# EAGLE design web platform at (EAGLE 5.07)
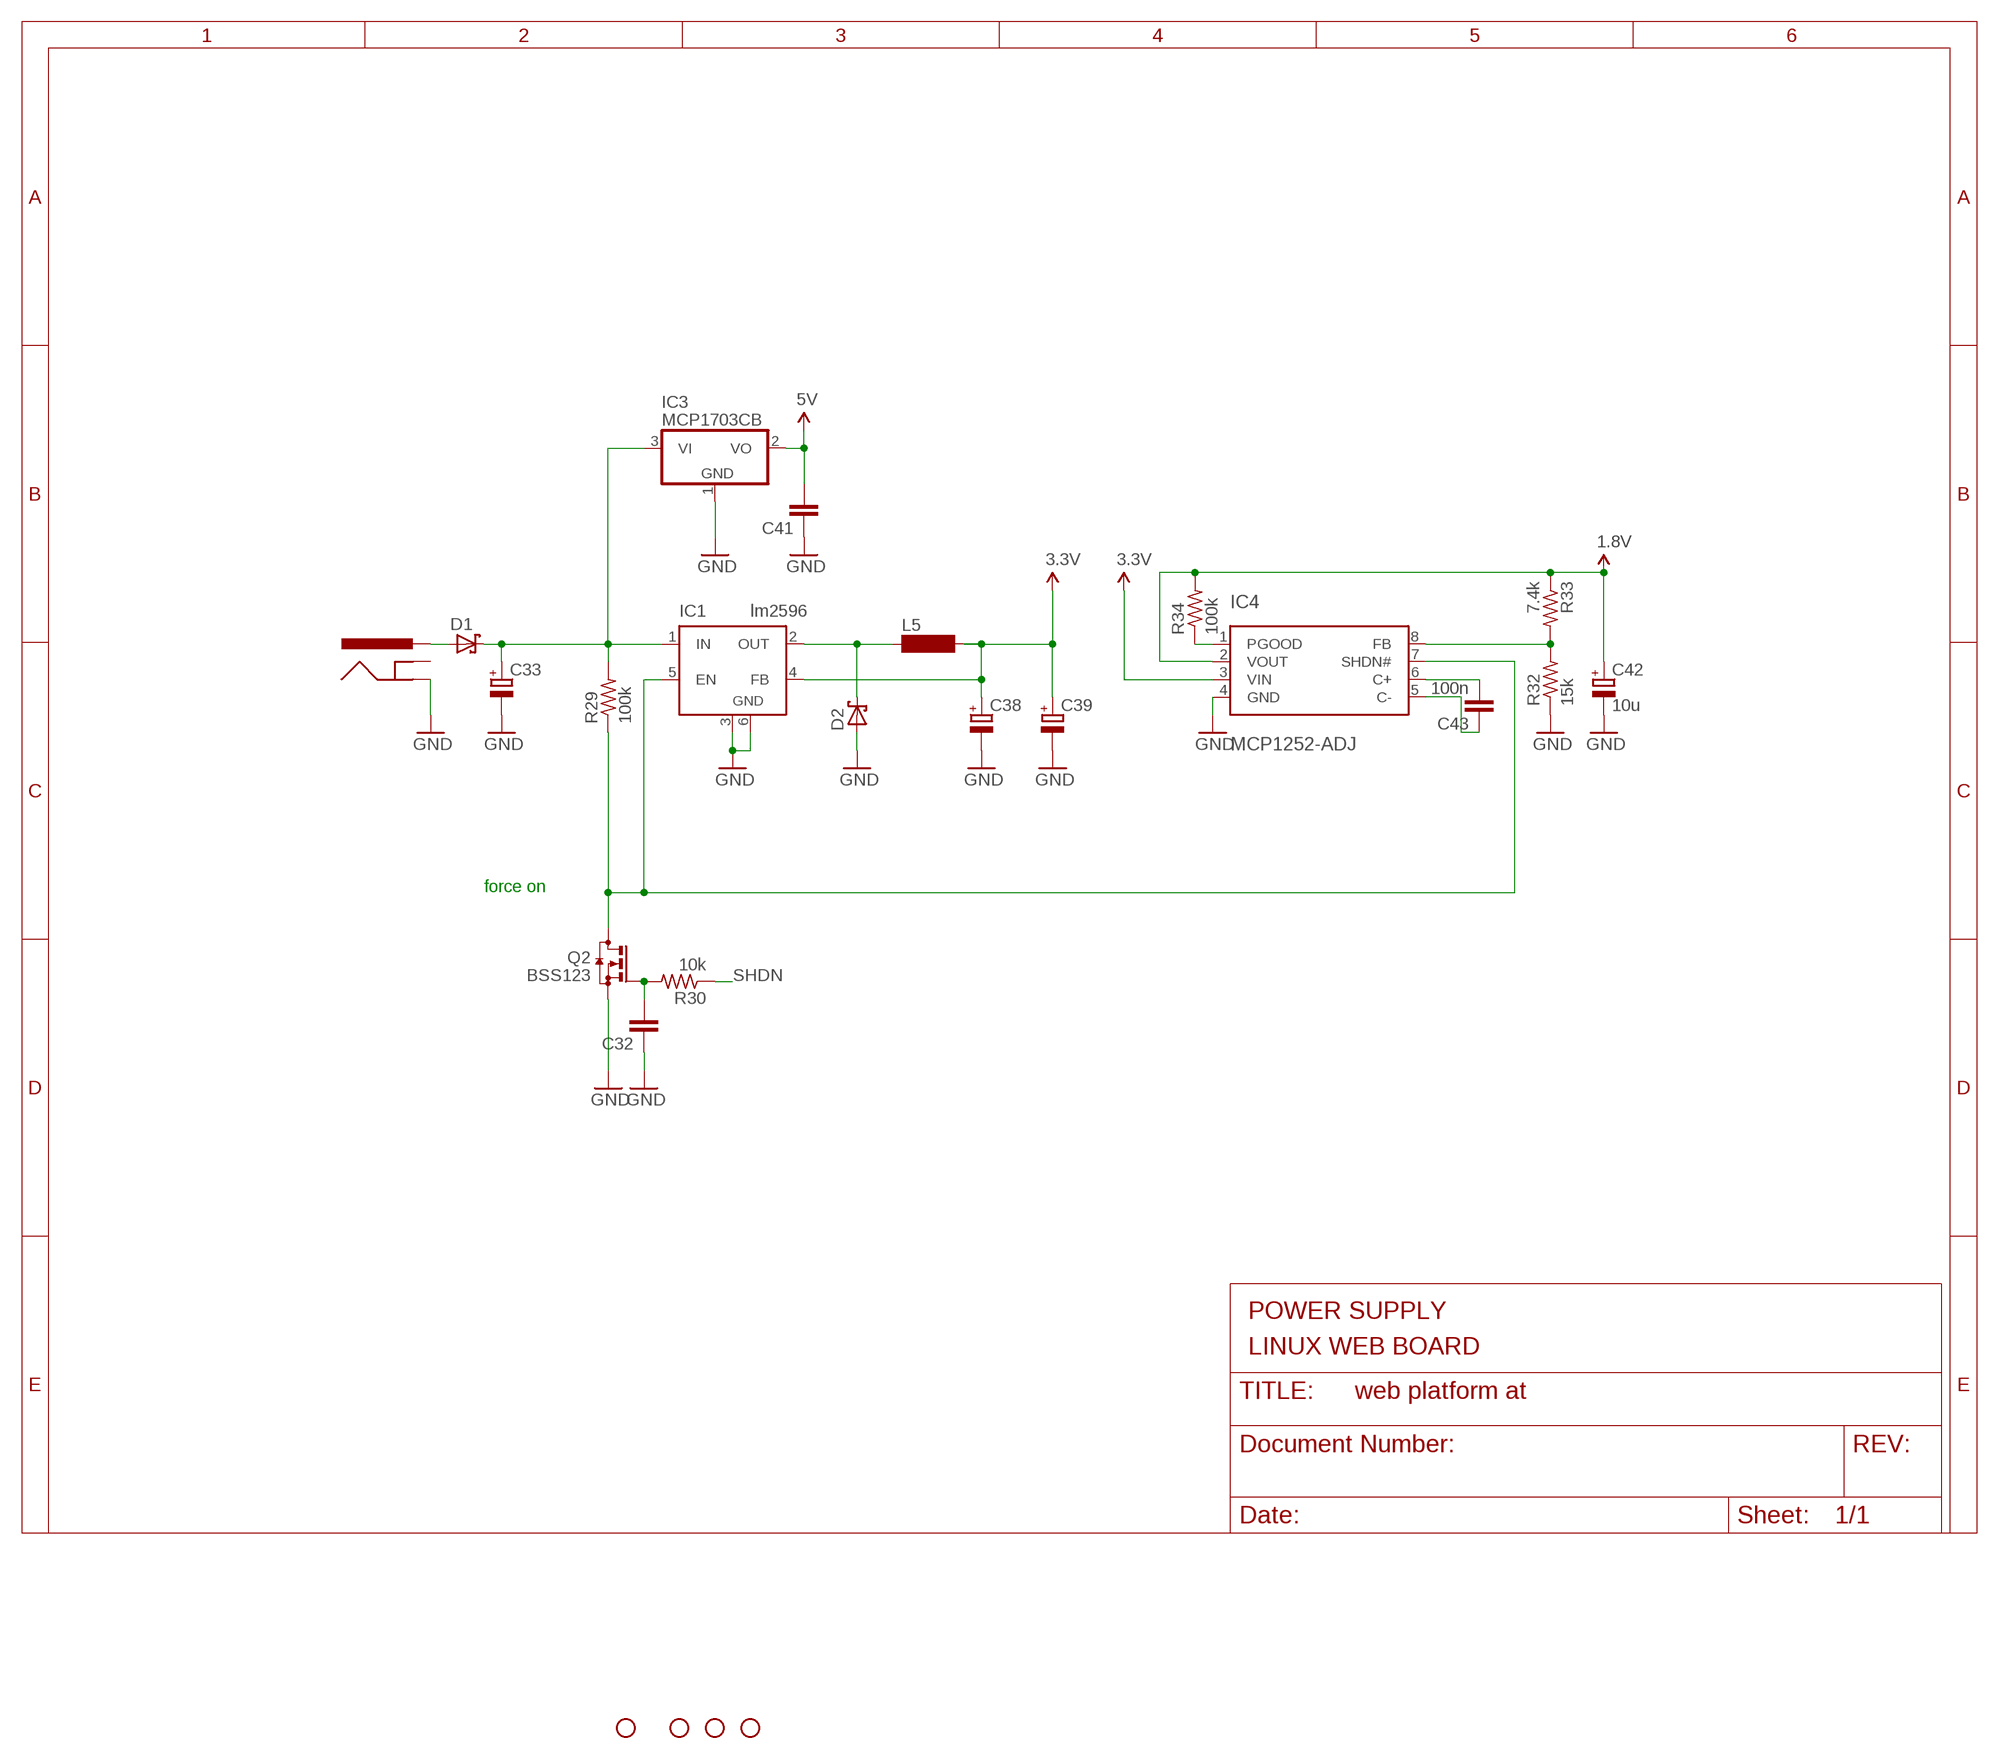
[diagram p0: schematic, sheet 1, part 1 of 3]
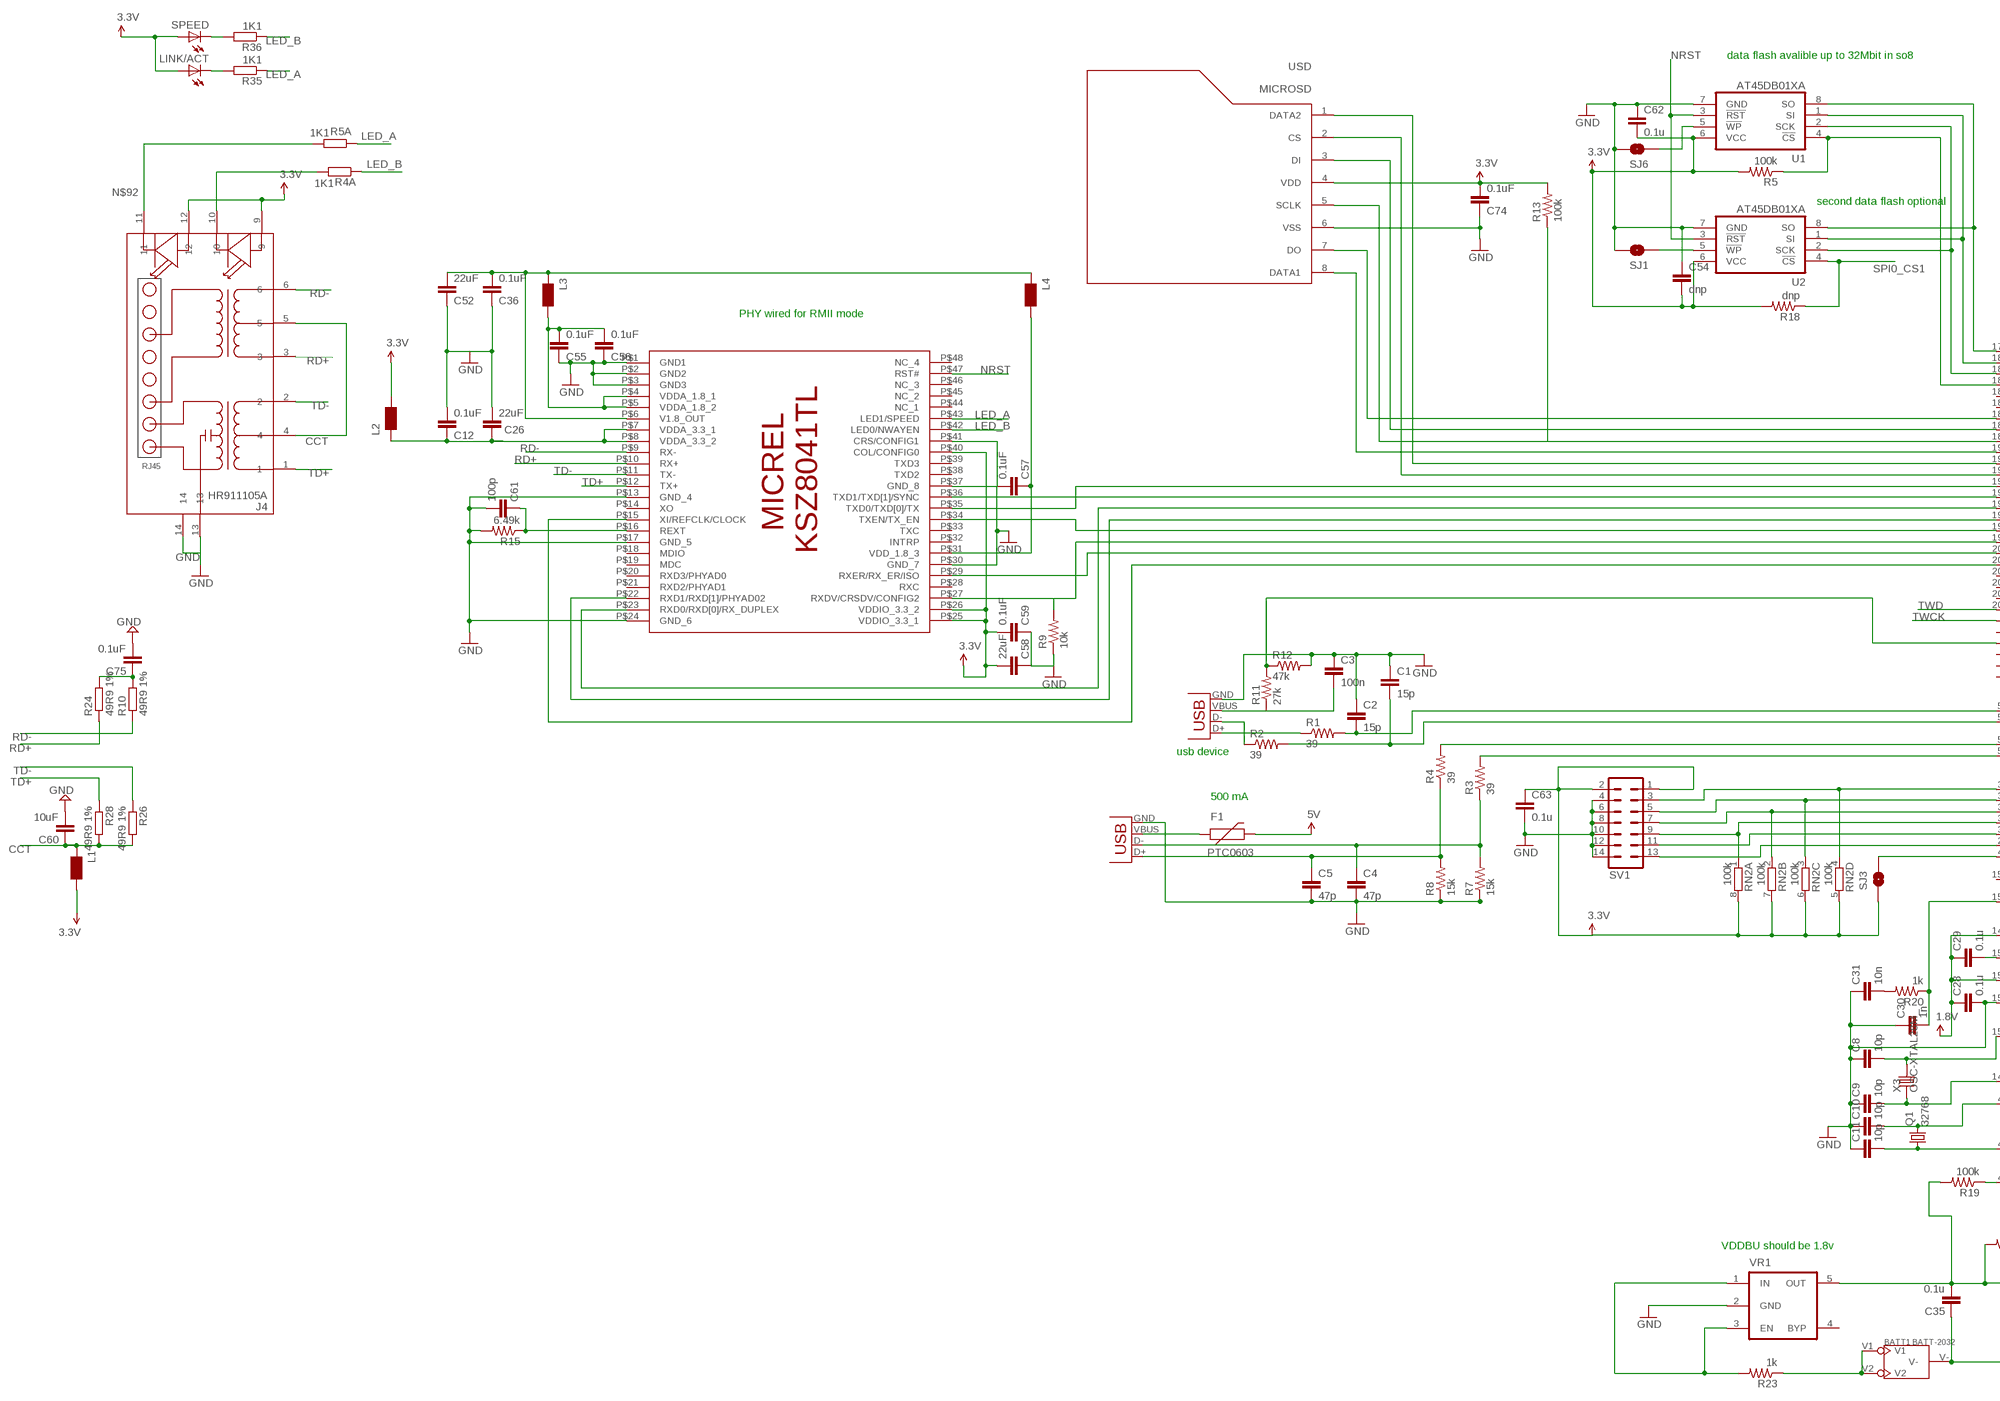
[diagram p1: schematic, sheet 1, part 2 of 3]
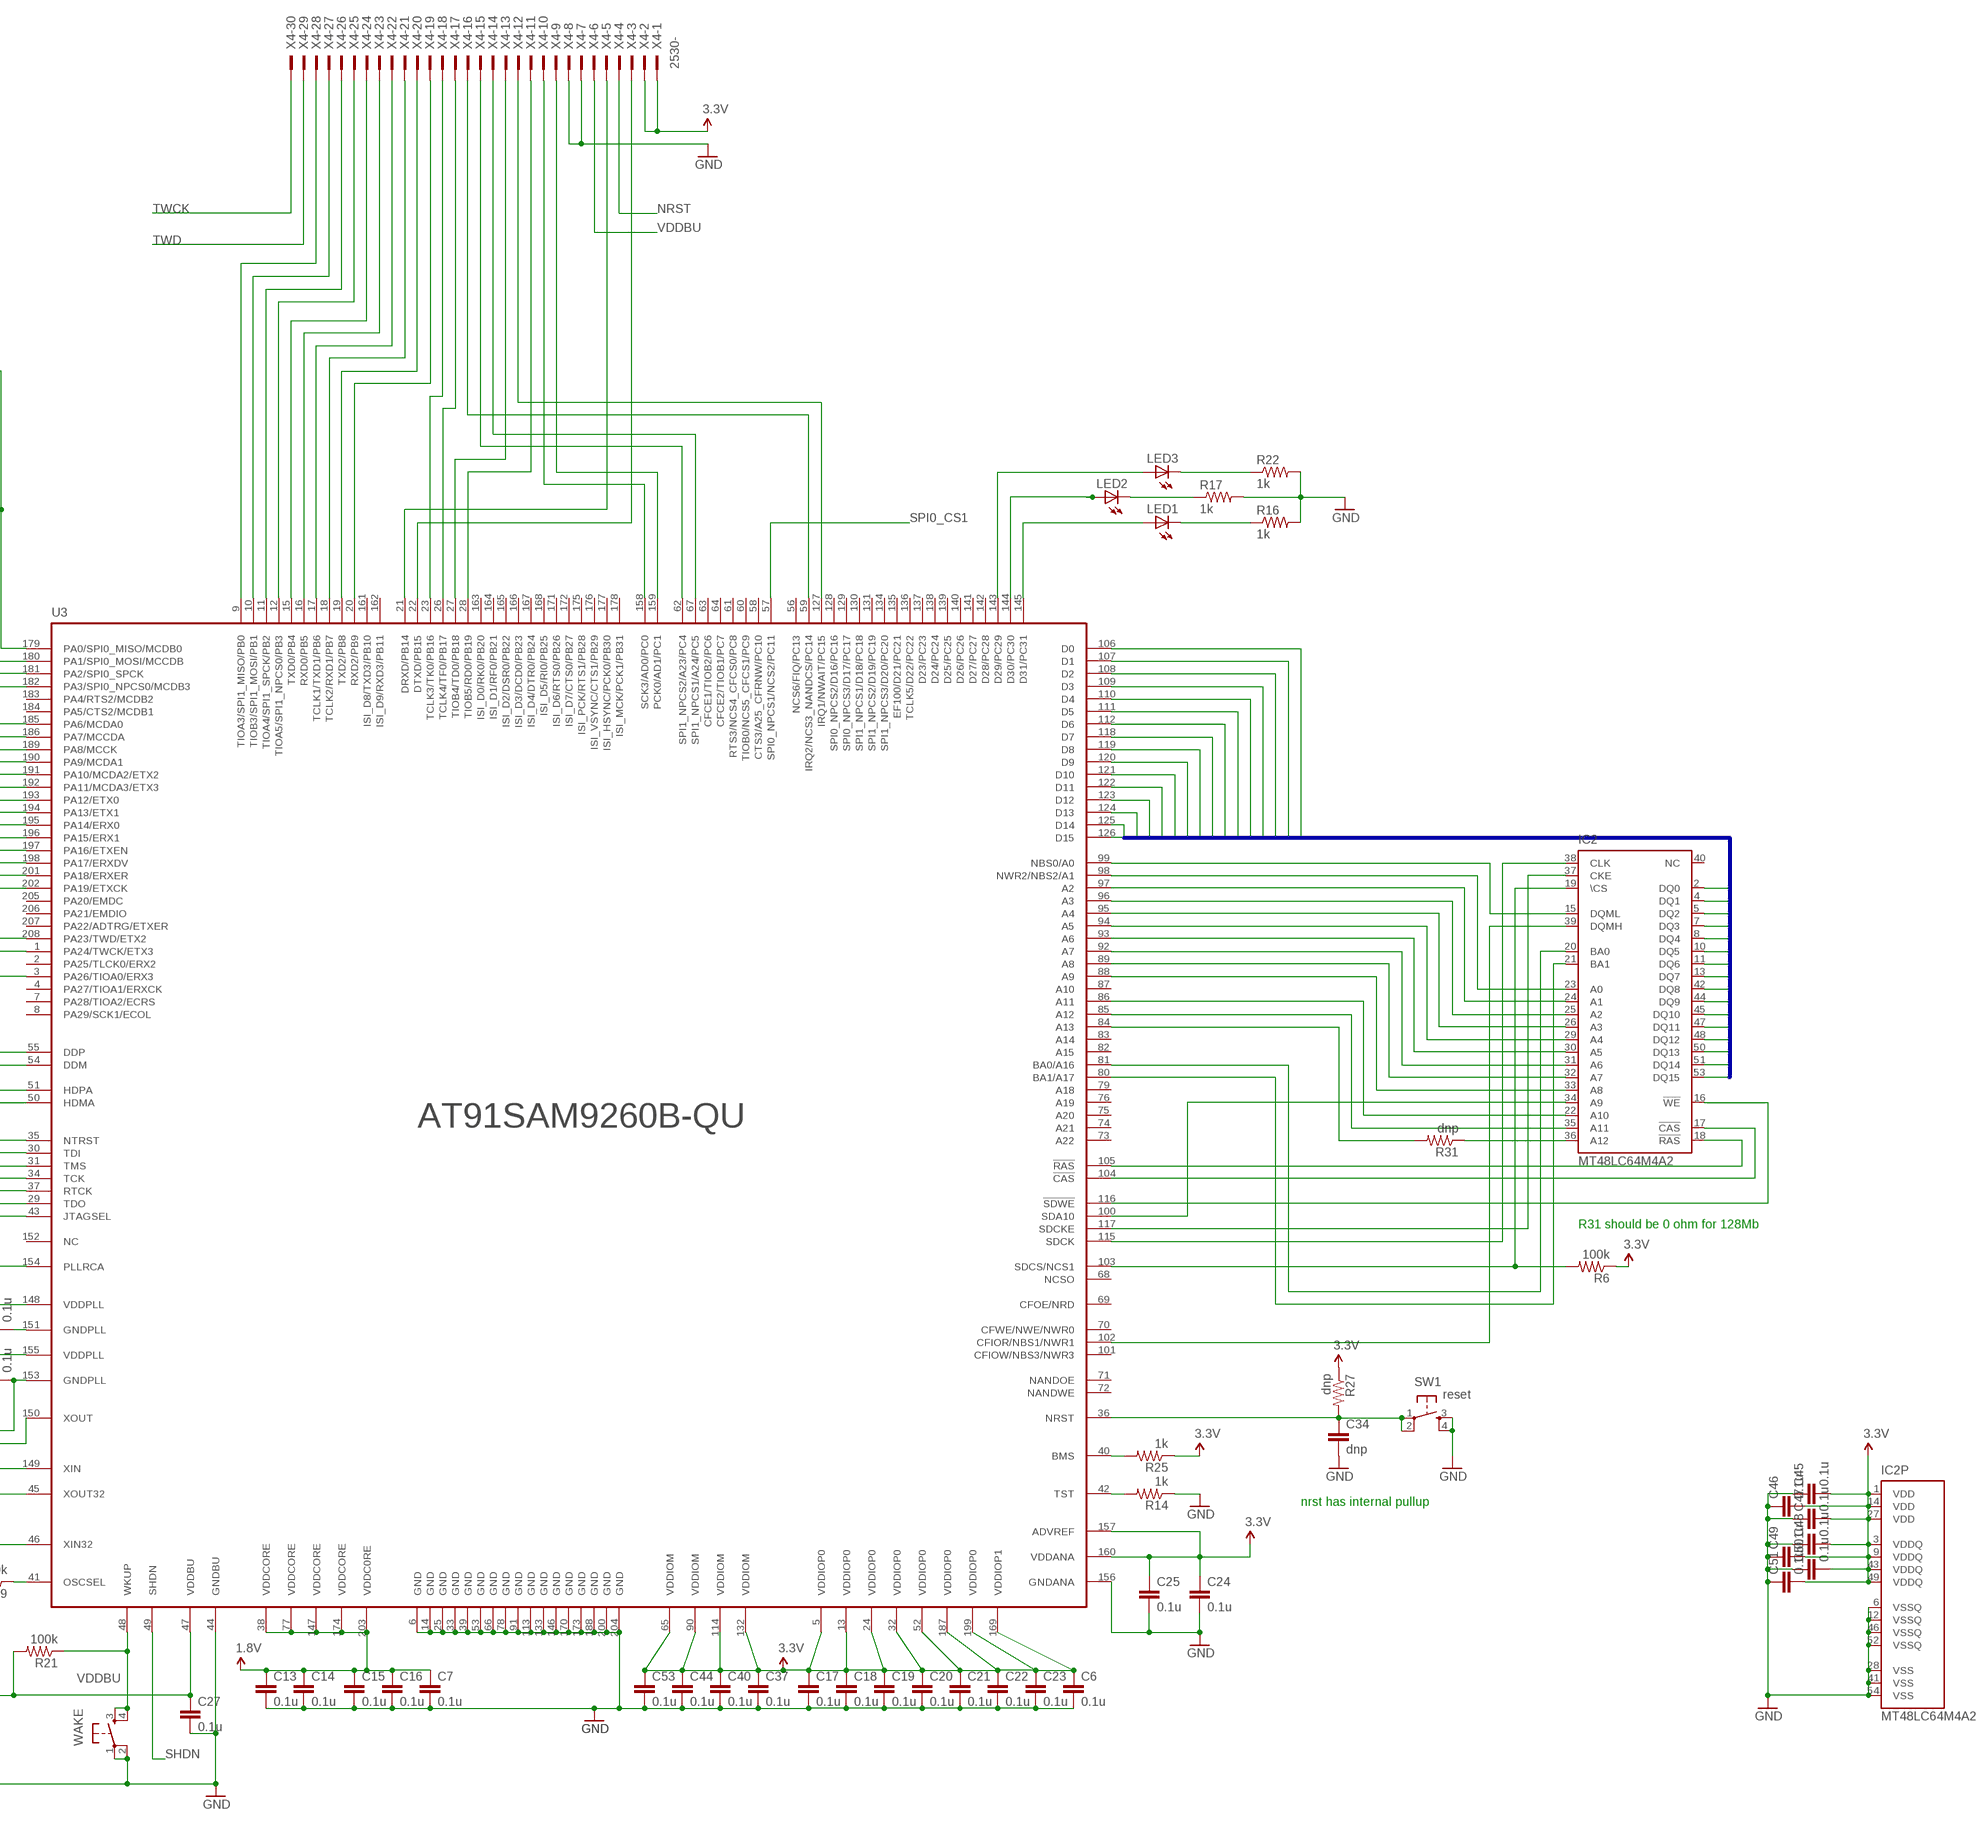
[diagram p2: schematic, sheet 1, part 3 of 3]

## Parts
BATT1  BATT-2032  [2032]
C1  15p  CAP0603-CAP  [0603-CAP]
C2  15p  CAP0603-CAP  [0603-CAP]
C3  100n  CAP0603-CAP  [0603-CAP]
C4  47p  CAP0603-CAP  [0603-CAP]
C5  47p  CAP0603-CAP  [0603-CAP]
C6  0.1u  CAP0603-CAP  [0603-CAP]
C7  0.1u  CAP0603-CAP  [0603-CAP]
C8  10p  CAP0603-CAP  [0603-CAP]
C9  10p  CAP0603-CAP  [0603-CAP]
C10  10p  CAP0603-CAP  [0603-CAP]
C11  10p  CAP0603-CAP  [0603-CAP]
C12  0.1uF  C-EUC0603  [C0603]
C13  0.1u  CAP0603-CAP  [0603-CAP]
C14  0.1u  CAP0603-CAP  [0603-CAP]
C15  0.1u  CAP0603-CAP  [0603-CAP]
C16  0.1u  CAP0603-CAP  [0603-CAP]
C17  0.1u  CAP0603-CAP  [0603-CAP]
C18  0.1u  CAP0603-CAP  [0603-CAP]
C19  0.1u  CAP0603-CAP  [0603-CAP]
C20  0.1u  CAP0603-CAP  [0603-CAP]
C21  0.1u  CAP0603-CAP  [0603-CAP]
C22  0.1u  CAP0603-CAP  [0603-CAP]
C23  0.1u  CAP0603-CAP  [0603-CAP]
C24  0.1u  CAP0603-CAP  [0603-CAP]
C25  0.1u  CAP0603-CAP  [0603-CAP]
C26  22uF  C-EUC0603  [C0603]
C27  0.1u  CAP0603-CAP  [0603-CAP]
C28  0.1u  CAP0603-CAP  [0603-CAP]
C29  0.1u  CAP0603-CAP  [0603-CAP]
C30  1n  CAP0603-CAP  [0603-CAP]
C31  10n  CAP0603-CAP  [0603-CAP]
C32  CAPC603  [C603]
C33  CAP_POLSMC_B  [SMC_B]
C34  dnp  CAP0603-CAP  [0603-CAP]
C35  0.1u  CAP0603-CAP  [0603-CAP]
C36  0.1uF  C-EUC0603  [C0603]
C37  0.1u  CAP0603-CAP  [0603-CAP]
C38  CAP_POLCASE_A  [CASE_A]
C39  CAP_POLSMC_B  [SMC_B]
C40  0.1u  CAP0603-CAP  [0603-CAP]
C41  CAPC603  [C603]
C42  10u  CAP_POLSMC_B  [SMC_B]
C43  100n  CAPC603  [C603]
C44  0.1u  CAP0603-CAP  [0603-CAP]
C45  0.1u  CAP0603-CAP  [0603-CAP]
C46  0.1u  CAP0603-CAP  [0603-CAP]
C47  0.1u  CAP0603-CAP  [0603-CAP]
C48  0.1u  CAP0603-CAP  [0603-CAP]
C49  0.1u  CAP0603-CAP  [0603-CAP]
C50  0.1u  CAP0603-CAP  [0603-CAP]
C51  0.1u  CAP0603-CAP  [0603-CAP]
C52  22uF  C-EUC0603  [C0603]
C53  0.1u  CAP0603-CAP  [0603-CAP]
C54  dnp  CAP0603-CAP  [0603-CAP]
C55  0.1uF  C-EUC0603  [C0603]
C56  0.1uF  C-EUC0603  [C0603]
C57  0.1uF  C-EUC0603  [C0603]
C58  22uF  C-EUC0603  [C0603]
C59  0.1uF  C-EUC0603  [C0603]
C60  10uF  C-EUC0603  [C0603]
C61  100p  C-EUC0603  [C0603]
C62  0.1u  CAP0603-CAP  [0603-CAP]
C63  0.1u  CAP0603-CAP  [0603-CAP]
C74  0.1uF  C-EUC0603  [C0603]
C75  0.1uF  C-EUC0603  [C0603]
D1  SCHOTTKY-DIODESMD  [SMB]
D2  SCHOTTKY-DIODESMD  [SMB]
F1  PTC0603  [0603]
IC1  lm2596  LM2596S  [TO263-5]
IC2  MT48LC64M4A2  [TSOP54-400]
IC3  MCP1703CB  [SOT23]
IC4  MCP1252-ADJ  [MSOP8]
J4  HR911105A  [HR911105A]
JP1  STAND-OFF  [STAND-OFF]
JP2  STAND-OFF  [STAND-OFF]
JP3  STAND-OFF  [STAND-OFF]
JP4  STAND-OFF  [STAND-OFF]
L1  WE-KIL_0805  [WE-KI_0805_B]
L2  WE-KIL_0805  [WE-KI_0805_B]
L3  WE-KIL_0805  [WE-KI_0805_B]
L4  WE-KIL_0805  [WE-KI_0805_B]
L5  MS85  [MS85]
LED1  LEDCHIPLED_0805  [CHIPLED_0805]
LED2  LEDCHIPLED_0805  [CHIPLED_0805]
LED3  LEDCHIPLED_0805  [CHIPLED_0805]
LINK/ACT  LEDCHIPLED_0805  [CHIPLED_0805]
Q1  32768  CRYSTALTC26H  [TC26H]
Q2  BSS123  [SOT23]
R1  39  R-US_R0603  [R0603]
R2  39  R-US_R0603  [R0603]
R3  39  R-US_R0603  [R0603]
R4  39  R-US_R0603  [R0603]
R4A  1K1  R-EU_R0603  [R0603]
R5  100k  R-US_R0603  [R0603]
R5A  1K1  R-EU_R0603  [R0603]
R6  100k  R-US_R0603  [R0603]
R7  15k  R-US_R0603  [R0603]
R8  15k  R-US_R0603  [R0603]
R9  10k  R-US_R0603  [R0603]
R10  49R9 1%  R-EU_R0603  [R0603]
R11  27k  R-US_R0603  [R0603]
R12  47k  R-US_R0603  [R0603]
R13  100k  R-US_R0603  [R0603]
R14  1k  R-US_R0603  [R0603]
R15  6.49k  R-US_R0603  [R0603]
R16  1k  R-US_R0603  [R0603]
R17  1k  R-US_R0603  [R0603]
R18  dnp  R-US_R0603  [R0603]
R19  100k  R-US_R0603  [R0603]
R20  1k  R-US_R0603  [R0603]
R21  100k  R-US_R0603  [R0603]
R22  1k  R-US_R0603  [R0603]
R23  1k  R-US_R0603  [R0603]
R24  49R9 1%  R-EU_R0603  [R0603]
R25  1k  R-US_R0603  [R0603]
R26  49R9 1%  R-EU_R0603  [R0603]
R27  dnp  R-US_R0603  [R0603]
R28  49R9 1%  R-EU_R0603  [R0603]
R29  100k  R-US_R0603  [R0603]
R30  10k  R-US_R0603  [R0603]
R31  dnp  R-US_R0603  [R0603]
R32  15k  R-US_R0603  [R0603]
R33  7.4k  R-US_R0603  [R0603]
R34  100k  R-US_R0603  [R0603]
R35  1K1  R-EU_R0603  [R0603]
R36  1K1  R-EU_R0603  [R0603]
RN2  100k  RNETWORK  [RN8P-4R-CRA06S]
SJ1  SOLDERJUMPERNO  [SJ_2S-NO]
SJ3  SOLDERJUMPERNO  [SJ_2S-NO]
SJ6  SOLDERJUMPERNO  [SJ_2S-NO]
SPEED  LEDCHIPLED_0805  [CHIPLED_0805]
SV1  MA07-2  [MA07-2]
SW1  reset  SW-SMD-SMALL  [TACT_SWITCH_SMALL]
U1  AT45DB01XA  [SO08W]
U2  AT45DB01XA  [SO08W]
U3  AT91SAM9260B-QU  [PQFP208]
U$1  KSZ8041TL  [48PIN-TQFN]
U$2  POWER_JACKSMD  [POWER_JACK_SMD]
USD  MICROSD  [MICROSD]
VR1  MIC5205  [SOT-23-5]
WAKE  SW-SMD-SMALL  [TACT_SWITCH_SMALL]
X1  USB-MB-S  [USB-MB-S]
X2  USB-A-H  [USB-A-H]
X3  OSC-XTAL28M_  [5X8]
X4  2530-  [PAK100/2500-30]

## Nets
1.8V: C7.1 C13.1 C14.1 C15.1 C16.1 C28.1 C29.1 C42.+ IC4.2(VOUT) R33.1 R34.2 U3.38(VDDCORE) U3.77(VDDCORE) U3.147(VDDCORE) U3.148(VDDPLL) U3.155(VDDPLL) U3.174(VDDCORE) U3.203(VDDC0RE)
3.3V: C6.1 C17.1 C18.1 C19.1 C20.1 C21.1 C22.1 C23.1 C24.1 C25.1 C37.1 C38.+ C39.+ C40.1 C44.1 C45.2 C46.2 C47.2 C48.2 C49.2 C50.2 C51.2 C53.1 C54.2 C58.1 C59.1 C62.2 C63.1 C74.1 IC1.4(FB) IC2.1(VDD) IC2.3(VDDQ) IC2.9(VDDQ) IC2.14(VDD) IC2.27(VDD) IC2.43(VDDQ) IC2.49(VDDQ) IC4.3(VIN) J4.9 J4.12 L1.1 L2.1 L5.2 LINK/ACT.A R5.2 R6.1 R13.2 R18.2 R25.1 R27.1 RN2.5 RN2.6 RN2.7 RN2.8 SJ3.1 SPEED.A SV1.1 SV1.2 U1.6(VCC) U2.6(VCC) U3.5(VDDIOP0) U3.13(VDDIOP0) U3.24(VDDIOP0) U3.32(VDDIOP0) U3.52(VDDIOP0) U3.65(VDDIOM) U3.90(VDDIOM) U3.114(VDDIOM) U3.132(VDDIOM) U3.157(ADVREF) U3.160(VDDANA) U3.169(VDDIOP1) U3.187(VDDIOP0) U3.199(VDDIOP0) U$1.P$25(VDDIO_3.3_1) U$1.P$26(VDDIO_3.3_2) U$1.P$40(COL/CONFIG0) USD.4(VDD) X4.1 X4.2
5V: C41.2 F1.2 IC3.2(VO)
CCT: C60.1 J4.4 J4.5 L1.2 R26.2 R28.2
D0: IC2.2(DQ0) U3.106(D0)
D1: IC2.4(DQ1) U3.107(D1)
D2: IC2.5(DQ2) U3.108(D2)
D3: IC2.7(DQ3) U3.109(D3)
D4: IC2.8(DQ4) U3.110(D4)
D5: IC2.10(DQ5) U3.111(D5)
D6: IC2.11(DQ6) U3.112(D6)
D7: IC2.13(DQ7) U3.118(D7)
D8: IC2.42(DQ8) U3.119(D8)
D9: IC2.44(DQ9) U3.120(D9)
D10: IC2.45(DQ10) U3.121(D10)
D11: IC2.47(DQ11) U3.122(D11)
D12: IC2.48(DQ12) U3.123(D12)
D13: IC2.50(DQ13) U3.124(D13)
D14: IC2.51(DQ14) U3.125(D14)
D15: IC2.53(DQ15) U3.126(D15)
GND: BATT1.V- C1.1 C2.1 C3.1 C4.2 C5.2 C6.2 C7.2 C8.1 C9.1 C10.1 C11.1 C12.1 C13.2 C14.2 C15.2 C16.2 C17.2 C18.2 C19.2 C20.2 C21.2 C22.2 C23.2 C24.2 C25.2 C26.1 C27.2 C28.2 C30.1 C31.1 C32.1 C33.- C34.2 C35.1 C36.2 C37.2 C38.- C39.- C40.2 C41.1 C42.- C44.2 C45.1 C46.1 C47.1 C48.1 C49.1 C50.1 C51.1 C52.2 C53.2 C54.1 C55.2 C56.2 C57.1 C58.2 C59.2 C60.2 C61.1 C62.1 C63.2 C74.2 C75.2 D2.A IC1.3(GND) IC1.6(GND) IC2.6(VSSQ) IC2.12(VSSQ) IC2.28(VSS) IC2.41(VSS) IC2.46(VSSQ) IC2.52(VSSQ) IC2.54(VSS) IC3.1(GND) IC4.4(GND) J4.13 J4.14 Q2.2(S) R7.1 R8.1 R9.1 R12.2 R14.1 R15.2 R16.2 R17.2 R22.2 R32.1 SJ1.2 SJ6.2 SV1.4 SV1.6 SV1.8 SV1.10 SV1.12 SV1.14 SW1.3 SW1.4 U1.7(GND) U2.7(GND) U3.6(GND) U3.14(GND) U3.25(GND) U3.33(GND) U3.39(GND) U3.44(GNDBU) U3.53(GND) U3.66(GND) U3.78(GND) U3.91(GND) U3.113(GND) U3.133(GND) U3.146(GND) U3.153(GNDPLL) U3.156(GNDANA) U3.170(GND) U3.173(GND) U3.188(GND) U3.200(GND) U3.204(GND) U$1.P$1(GND1) U$1.P$2(GND2) U$1.P$3(GND3) U$1.P$13(GND_4) U$1.P$17(GND_5) U$1.P$24(GND_6) U$1.P$30(GND_7) U$1.P$37(GND_8) U$1.P$41(CRS/CONFIG1) U$2.P$4(GND) USD.6(VSS) VR1.2(GND) WAKE.1 WAKE.2 X1.GND X2.GND X4.7 X4.8
LED_A: R5A.1 R35.1 U$1.P$43(LED1/SPEED)
LED_B: R4A.1 R36.1 U$1.P$42(LED0/NWAYEN)
LED_SPEED: J4.10 R4A.2
N$1: RN2.4 SV1.3 U3.35(NTRST)
N$2: C10.2 Q1.2 U3.45(XOUT32)
N$3: C11.2 Q1.1 U3.46(XIN32)
N$4: C9.2 U3.149(XIN) X3.1(X1)
N$5: C8.2 U3.150(XOUT) X3.2(X2)
N$6: C29.2 U3.151(GNDPLL)
N$7: IC2.18(!RAS) U3.105(!RAS)
N$8: IC2.17(!CAS) U3.104(!CAS)
N$9: IC2.16(!WE) U3.116(!SDWE)
N$10: IC2.15(DQML) U3.99(NBS0/A0)
N$11: IC2.23(A0) U3.98(NWR2/NBS2/A1)
N$12: IC2.24(A1) U3.97(A2)
N$29: IC2.20(BA0) U3.81(BA0/A16)
N$30: IC2.21(BA1) U3.80(BA1/A17)
N$31: IC2.38(CLK) U3.115(SDCK)
N$32: IC2.25(A2) U3.96(A3)
N$33: IC2.26(A3) U3.95(A4)
N$34: U3.191(PA10/MCDA2/ETX2) USD.1(DATA2)
N$35: C5.1 R4.1 R8.2 X2.D+
N$36: R4.2 U3.51(HDPA)
N$37: SJ3.2 U3.43(JTAGSEL)
N$38: R3.2 U3.50(HDMA)
N$39: U1.2(SCK) U2.2(SCK) U3.181(PA2/SPI0_SPCK)
N$40: IC1.5(EN) IC4.7(SHDN#) Q2.3(D) R29.1
N$41: U1.1(SI) U2.1(SI) U3.180(PA1/SPI0_MOSI/MCCDB)
N$42: C61.2 R15.1 U$1.P$16(REXT)
N$43: U3.23(TCLK3/TK0/PB16) X4.18
N$44: U3.26(TCLK4/TF0/PB17) X4.17
N$45: U1.8(SO) U2.8(SO) U3.179(PA0/SPI0_MISO/MCDB0)
N$46: U3.9(TIOA3/SPI1_MISO/PB0) X4.28
N$47: SV1.11 U3.37(RTCK)
N$48: RN2.3 SV1.5 U3.30(TDI)
N$49: RN2.2 SV1.7 U3.31(TMS)
N$50: RN2.1 SV1.9 U3.34(TCK)
N$51: SJ1.1 U2.5(!WP!)
N$52: U3.27(TIOB4/TD0/PB18) X4.13
N$53: IC2.29(A4) U3.94(A5)
N$54: IC2.30(A5) U3.93(A6)
N$55: IC2.31(A6) U3.92(A7)
N$56: IC2.32(A7) U3.89(A8)
N$57: IC2.33(A8) U3.88(A9)
N$58: IC2.34(A9) U3.100(SDA10)
N$59: IC2.22(A10) U3.86(A11)
N$60: IC2.35(A11) U3.85(A12)
N$61: R31.2 U3.84(A13)
N$62: IC2.36(A12) R31.1
N$63: R19.1 U3.41(OSCSEL)
N$64: R5.1 U1.4(!CS!) U3.182(PA3/SPI0_NPCS0/MCDB3)
N$65: U3.28(TIOB5/RD0/PB19) X4.11
N$66: C75.1 R10.2 R24.2
N$67: C12.2 C26.2 L2.2 U$1.P$7(VDDA_3.3_1) U$1.P$8(VDDA_3.3_2)
N$68: C32.2 Q2.1(G) R30.2
N$69: U3.202(PA19/ETXCK) U$1.P$15(XI/REFCLK/CLOCK)
N$70: R9.2 U3.198(PA17/ERXDV) U$1.P$27(RXDV/CRSDV/CONFIG2)
N$71: IC2.39(DQMH) U3.102(CFIOR/NBS1/NWR1)
N$72: U3.195(PA14/ERX0) U$1.P$23(RXD0/RXD[0]/RX_DUPLEX)
N$73: U3.196(PA15/ERX1) U$1.P$22(RXD1/RXD[1]/PHYAD02)
N$74: U3.201(PA18/ERXER) U$1.P$29(RXER/RX_ER/ISO)
N$75: SJ6.1 U1.5(!WP!)
N$76: U3.197(PA16/ETXEN) U$1.P$34(TXEN/TX_EN)
N$77: U3.193(PA12/ETX0) U$1.P$35(TXD0/TXD[0]/TX)
N$78: U3.194(PA13/ETX1) U$1.P$36(TXD1/TXD[1]/SYNC)
N$79: R25.2 U3.40(BMS)
N$80: LED3.A U3.143(D29/PC29)
N$81: R36.2 SPEED.C
N$82: U3.10(TIOB3/SPI1_MOSI/PB1) X4.27
N$83: R14.2 U3.42(TST)
N$84: IC2.19(\CS) R6.2 U3.103(SDCS/NCS1)
N$85: IC2.37(CKE) U3.117(SDCKE)
N$86: C55.1 C56.1 L3.1 U$1.P$4(VDDA_1.8_1) U$1.P$5(VDDA_1.8_2)
N$87: C57.2 L4.1 U$1.P$31(VDD_1.8_3)
N$88: LINK/ACT.C R35.2
N$89: C36.1 C52.1 L3.2 L4.2 U$1.P$6(V1.8_OUT)
N$90: LED2.A U3.144(D30/PC30)
N$91: R23.2 VR1.1(IN) VR1.3(EN)
N$92: J4.11 R5A.2
N$94: LED1.A U3.145(D31/PC31)
N$95: LED1.C R16.1
N$96: C1.2 R2.2 U3.54(DDM)
N$97: C2.2 R1.2 U3.55(DDP)
N$98: LED2.C R17.1
N$99: R2.1 X1.D-
N$100: R1.1 X1.D+
N$101: LED3.C R22.1
N$102: C3.2 R11.1 X1.VBUS
N$103: U3.11(TIOA4/SPI1_SPCK/PB2) X4.26
N$104: U3.12(TIOA5/SPI1_NPCS0/PB3) X4.25
N$106: BATT1.V1 BATT1.V2 R23.1
N$107: U3.190(PA9/MCDA1) USD.8(DATA1)
N$108: U3.15(TXD0/PB4) X4.24
N$109: U3.16(RXD0/PB5) X4.23
N$110: U3.17(TCLK1/TXD1/PB6) X4.22
N$111: U3.18(TCLK2/RXD1/PB7) X4.21
N$112: U3.19(TXD2/PB8) X4.20
N$113: U3.20(RXD2/PB9) X4.19
N$114: U3.158(SCK3/AD0/PC0) X4.10
N$115: U3.159(PCK0/AD1/PC1) X4.9
N$116: U3.21(DRXD/PB14) X4.5
N$117: U3.22(DTXD/PB15) X4.3
N$118: U3.62(SPI1_NPCS2/A23/PC4) X4.15
N$119: C31.2 R20.2
N$120: C30.2 R20.1 U3.154(PLLRCA)
N$121: F1.1 X2.VBUS
N$122: U3.67(SPI1_NPCS1/A24/PC5) X4.14
N$123: U3.59(IRQ2/NCS3_NANDCS/PC14) X4.16
N$124: U3.127(IRQ1/NWAIT/PC15) X4.12
N$125: SV1.13 U3.29(TDO)
N$126: D1.A U$2.VIN0(PWR)
N$127: D2.C IC1.2(OUT) L5.1
N$130: C43.2 IC4.6(C+)
N$131: C43.1 IC4.5(C-)
N$132: IC4.8(FB) R32.2 R33.2
N$134: IC4.1(PGOOD) R34.1
N$164: R21.1 U3.48(WKUP) WAKE.3 WAKE.4
NRST: C34.1 R27.2 SW1.1 SW1.2 U1.3(!RST!) U2.3(!RST!) U3.36(NRST) U$1.P$47(RST#) X4.4
RD+: J4.3 R24.1 U$1.P$10(RX+)
RD-: J4.6 R10.1 U$1.P$9(RX-)
SDCLK: R13.1 U3.189(PA8/MCCK) USD.5(SCLK)
SDCS: U3.192(PA11/MCDA3/ETX3) USD.2(CS)
SDMISO: U3.185(PA6/MCDA0) USD.7(DO)
SDMOSI: U3.186(PA7/MCCDA) USD.3(DI)
SHDN: R30.1 U3.49(SHDN)
SPI0_CS1: R18.1 U2.4(!CS!) U3.57(SPI0_NPCS1/NCS2/PC11)
TD+: J4.1 R28.1 U$1.P$12(TX+)
TD-: J4.2 R26.1 U$1.P$11(TX-)
TWCK: U3.1(PA24/TWCK/ETX3) X4.30
TWD: U3.208(PA23/TWD/ETX2) X4.29
USB_D-: C4.1 R3.1 R7.2 X2.D-
USBDETECT: R11.2 R12.1 U3.3(PA26/TIOA0/ERX3)
VDDBU: C27.1 C35.2 R19.2 R21.2 U3.47(VDDBU) VR1.5(OUT) X4.6
VIN: C33.+ D1.C IC1.1(IN) IC3.3(VI) R29.2
Unconnected: IC2.40(NC) U3.2(PA25/TLCK0/ERX2) U3.4(PA27/TIOA1/ERXCK) U3.7(PA28/TIOA2/ECRS) U3.8(PA29/SCK1/ECOL) U3.56(NCS6/FIQ/PC13) U3.58(CTS3/A25_CFRNW/PC10) U3.60(TIOB0/NCS5_CFCS1/PC9) U3.61(RTS3/NCS4_CFCS0/PC8) U3.63(CFCE1/TIOB2/PC6) U3.64(CFCE2/TIOB1/PC7) U3.68(NCSO) U3.69(CFOE/NRD) U3.70(CFWE/NWE/NWR0) U3.71(NANDOE) U3.72(NANDWE) U3.73(A22) U3.74(A21) U3.75(A20) U3.76(A19) U3.79(A18) U3.82(A15) U3.83(A14) U3.87(A10) U3.101(CFIOW/NBS3/NWR3) U3.128(SPI0_NPCS2/D16/PC16) U3.129(SPI0_NPCS3/D17/PC17) U3.130(SPI1_NPCS1/D18/PC18) U3.131(SPI1_NPCS2/D19/PC19) U3.134(SPI1_NPCS3/D20/PC20) U3.135(EF100/D21/PC21) U3.136(TCLK5/D22/PC22) U3.137(D23/PC23) U3.138(D24/PC24) U3.139(D25/PC25) U3.140(D26/PC26) U3.141(D27/PC27) U3.142(D28/PC28) U3.152(NC) U3.161(ISI_D8/TXD3/PB10) U3.162(ISI_D9/RXD3/PB11) U3.163(ISI_D0/RK0/PB20) U3.164(ISI_D1/RF0/PB21) U3.165(ISI_D2/DSR0/PB22) U3.166(ISI_D3/DCD0/PB23) U3.167(ISI_D4/DTR0/PB24) U3.168(ISI_D5/RI0/PB25) U3.171(ISI_D6/RTS0/PB26) U3.172(ISI_D7/CTS0/PB27) U3.175(ISI_PCK/RTS1/PB28) U3.176(ISI_VSYNC/CTS1/PB29) U3.177(ISI_HSYNC/PCK0/PB30) U3.178(ISI_MCK/PCK1/PB31) U3.183(PA4/RTS2/MCDB2) U3.184(PA5/CTS2/MCDB1) U3.205(PA20/EMDC) U3.206(PA21/EMDIO) U3.207(PA22/ADTRG/ETXER) U$1.P$14(XO) U$1.P$18(MDIO) U$1.P$19(MDC) U$1.P$20(RXD3/PHYAD0) U$1.P$21(RXD2/PHYAD1) U$1.P$28(RXC) U$1.P$32(INTRP) U$1.P$33(TXC) U$1.P$38(TXD2) U$1.P$39(TXD3) U$1.P$44(NC_1) U$1.P$45(NC_2) U$1.P$46(NC_3) U$1.P$48(NC_4) U$2.GND VR1.4(BYP)

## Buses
D[0..15]

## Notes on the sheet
- force on
- POWER SUPPLY
- LINUX WEB BOARD
- data flash avalible up to 32Mbit in so8
- second data flash optional
- PHY wired for RMII mode
- usb device
- 500 mA
- R31 should be 0 ohm for 128Mb
- nrst has internal pullup
- VDDBU should be 1.8v

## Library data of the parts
BATT1 = dp_devices:BATT-2032
C1-C11 C13-C25 C27-C31 C34 C35 C37 C40 C44-C51 C53 C54 C62 C63 = SparkFun:CAP: Capacitor
C12 C26 C36 C52 C55-C61 C74 C75 = rcl:C-EU: CAPACITOR, European symbol
C32 C41 C43 = dp_devices:CAP
C33 C38 C39 C42 = dp_devices:CAP_POL
D1 D2 = diode:SCHOTTKY-DIODE: Schottky Diode
F1 = SparkFun:PTC: Resettable Fuse PTC
IC1 = linear:LM2596S: STEP-DOWN VOLTAGE REGULATOR
IC2 = memory-micron:MT48LC64M4A2: 256Mb: x16 SDRAM MT48LC64M4A2 - 16 Meg x 4 x 4 banks Source: http://download.micron.com/pdf/datasheets/dram/sdram/256MSDRAM.pdf
IC3 = linear:MCP1703: 250 mA, 16V, Low Quiescent Current LDO Regulator Source: http://ww1.microchip.com/downloads/en/DeviceDoc/22049b.pdf
IC4 = microchip-dspic:MCP1252-ADJ: Positive-Regulated Adjustable Charge Pump
J4 = CONNECTER:HR911105A
JP1-JP4 = SparkFun:STAND-OFF: Stand Off
L1-L4 = wuerth-elektronik:WE-KIL: SMD Wire Wound Ceramic Inductor WE-KIL
L5 = inductor-neosid:MS85: INDUCTOR
LED1-LED3 LINK/ACT SPEED = led:LED: LED
Q1 = crystal:CRYSTAL: CRYSTAL
Q2 = transistor-small-signal:BSS123: N-CHANNEL MOS FET
R1-R9 R11-R23 R25 R27 R29-R34 = resistor:R-US_: RESISTOR, American symbol
R4A R5A R10 R24 R26 R28 R35 R36 = rcl:R-EU_: RESISTOR, European symbol
RN2 = dp_devices:RNETWORK: 4 Resistor Array 0603
SJ1 SJ3 SJ6 = SparkFun:SOLDERJUMPER: Solder Jumper
SV1 = con-lstb:MA07-2: PIN HEADER
SW1 WAKE = dp_devices:SW-SMD-SMALL
U1 U2 = memory-atmel:AT45DB01X: EEPROM SPI bus serial
U3 = atmel-arm:AT91SAM9260B-QU: AT91SAM9260 MCU AT91 ARM-9 Thumb Microcontroller
U$1 = micrelphy:KSZ8041TL
U$2 = SparkFun-3-2-07:POWER_JACK: Power Jack This is the standard 5.5mm barrel jack for power. The PTH is the most common, proven, reliable, footprint. All others are experimental. The Slot footprint only works if the mill layer is transmitted to the PCB fab house so be warned. Spark Fun Electronics SKU : PType-BPJ. Mating wall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
USD = Seeed:MICROSD
VR1 = dp_devices:MIC5205: 150ma Low-Noise LDO Regulator
X1 X2 = con-usb:USB: USB Connectors
X3 = dp_devices:OSC-XTAL2
X4 = con-3m:2530-: 3M (TM) Pak 100 4-Wall Header Source: 3M

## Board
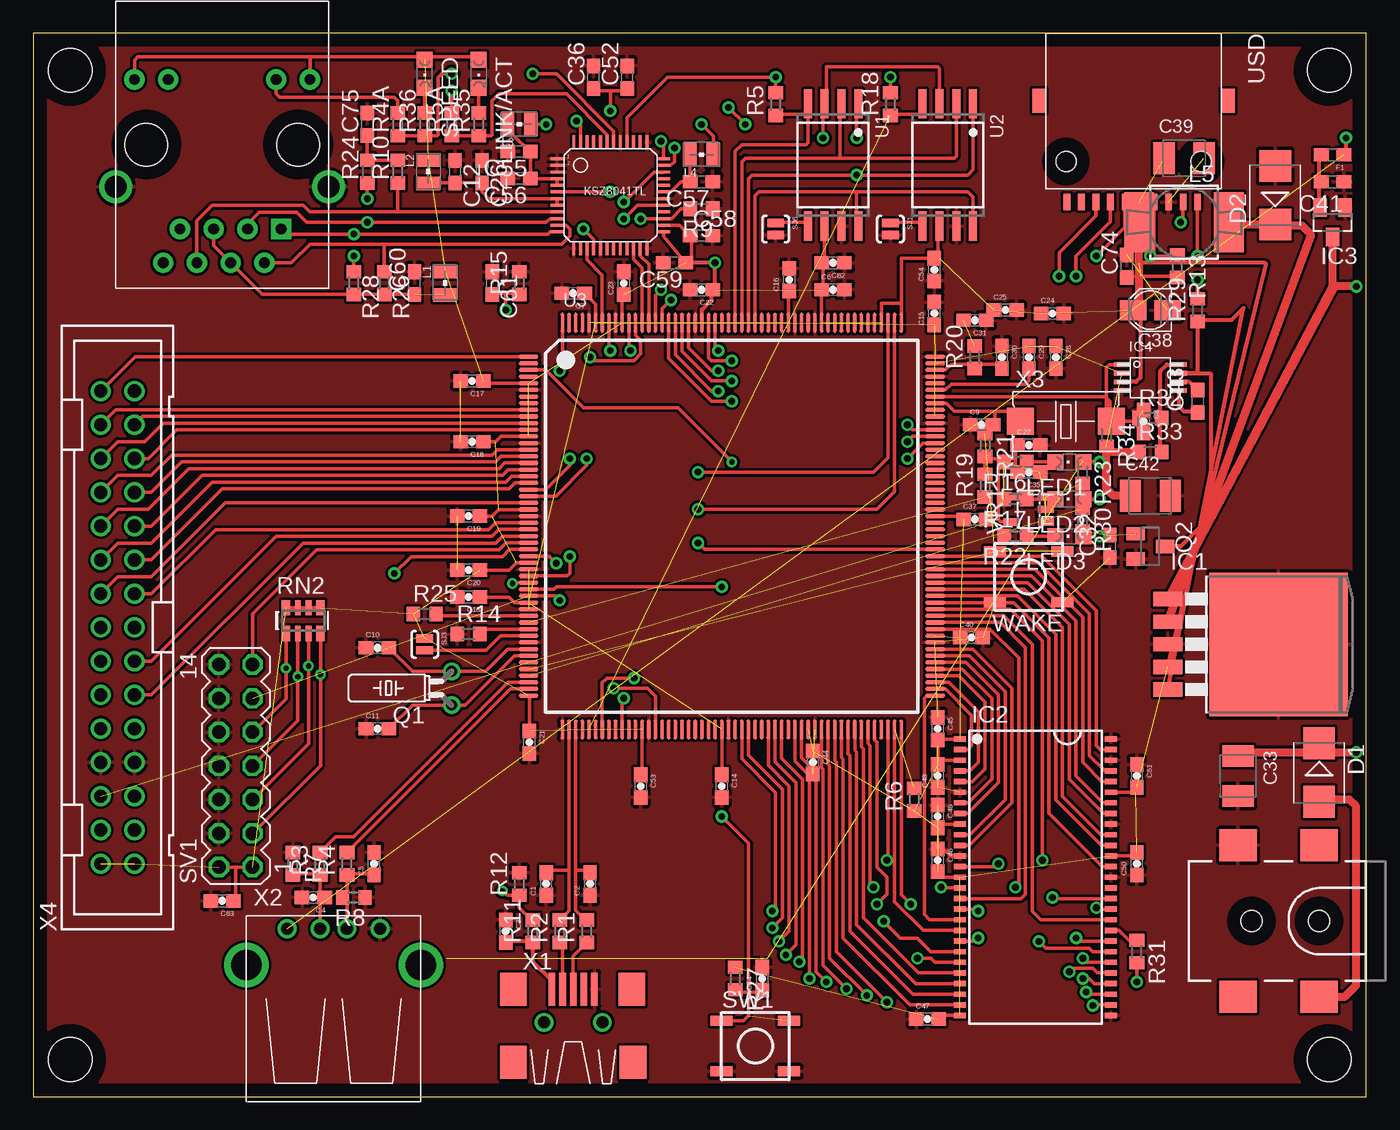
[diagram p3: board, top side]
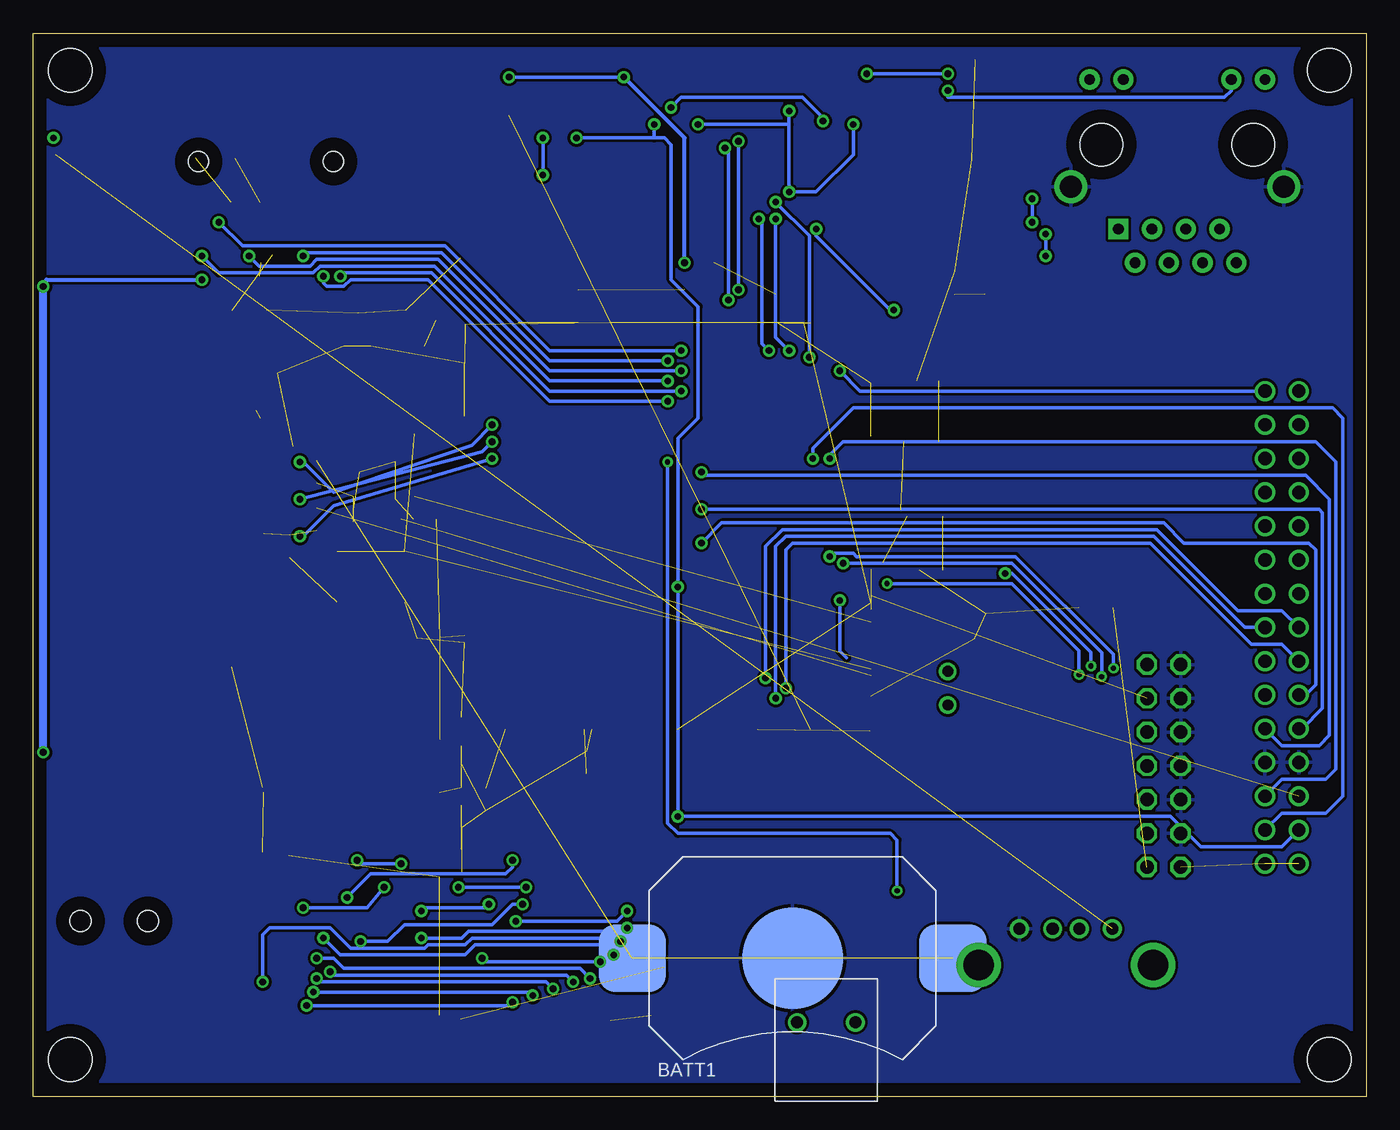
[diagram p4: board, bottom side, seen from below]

Size 100.33 x 80.01 mm. Coordinates in mm from the lower left corner, seen from the top.
Outline: 0,0 100.33,0 100.33,80.01 0,80.01 0,0
Copper layers (1*16): Top 0.035mm / dielectric 1.5mm / Bottom 0.035mm
Design rules "default": minimum track width 10mil, minimum drill 0.6mm, track to track 8mil, track to pad 8mil, pad to pad 8mil, via to via 8mil, smd to smd 8mil, copper to edge 40mil, drill to drill 8mil, minimum pad ring 10mil, minimum via ring 8mil, stop-mask expansion 4mil, vias tented up to drill 0mil, thermal gap 10mil

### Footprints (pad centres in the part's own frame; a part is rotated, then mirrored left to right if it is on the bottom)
2032 = smd 5.08 x 5.08: V1 -12.065,0; V2 12.065,0 | smd 7.62 x 7.62: V- 0,0
0603-CAP = smd 1.1 x 1: 1 -0.85,0; 2 0.85,0
C0603 = smd 1.1 x 1: 1 -0.85,0; 2 0.85,0
C603 = smd 1.1 x 1: 1 -0.85,0; 2 0.85,0
SMC_B = smd 1.6 x 2.4: + -1.5,0; - 1.5,0
CASE_A = smd 2 x 1.5: + 1.3,0; - -1.3,0
SMB = smd 2.4 x 2.4: A 2.2,0; C -2.2,0
0603 = smd 1.1 x 1: 1 -0.85,0; 2 0.85,0
TO263-5 = smd 1.067 x 2.159: 1 -3.404,-5.791; 2 -1.702,-5.791; 3 0,-5.791; 4 1.702,-5.791; 5 3.404,-5.791 | smd 10.8 x 10.41: 6 0,2.54
TSOP54-400 = smd 0.4 x 0.9: 1 -10.4,-5.68; 2 -9.6,-5.68; 3 -8.8,-5.68; 4 -8,-5.68; 5 -7.2,-5.68; 6 -6.4,-5.68; 7 -5.6,-5.68; 8 -4.8,-5.68; 9 -4,-5.68; 10 -3.2,-5.68; 11 -2.4,-5.68; 12 -1.6,-5.68; 13 -0.8,-5.68; 14 0,-5.68; 15 0.8,-5.68; 16 1.6,-5.68; 17 2.4,-5.68; 18 3.2,-5.68; 19 4,-5.68; 20 4.8,-5.68; 21 5.6,-5.68; 22 6.4,-5.68; 23 7.2,-5.68; 24 8,-5.68; 25 8.8,-5.68; 26 9.6,-5.68; 27 10.4,-5.68; 28 10.4,5.68; 29 9.6,5.68; 30 8.8,5.68; 31 8,5.68; 32 7.2,5.68; 33 6.4,5.68; 34 5.6,5.68; 35 4.8,5.68; 36 4,5.68; 37 3.2,5.68; 38 2.4,5.68; 39 1.6,5.68; 40 0.8,5.68; 41 0,5.68; 42 -0.8,5.68; 43 -1.6,5.68; 44 -2.4,5.68; 45 -3.2,5.68; 46 -4,5.68; 47 -4.8,5.68; 48 -5.6,5.68; 49 -6.4,5.68; 50 -7.2,5.68; 51 -8,5.68; 52 -8.8,5.68; 53 -9.6,5.68; 54 -10.4,5.68
SOT23 = smd 1 x 1.4: 1 -0.95,-1.1; 2 0.95,-1.1; 3 0,1.1
MSOP8 = smd 1.2 x 0.35: 1 -2.145,0.975; 2 -2.145,0.325; 3 -2.145,-0.325; 4 -2.145,-0.975; 5 2.145,-0.975; 6 2.145,-0.325; 7 2.145,0.325; 8 2.145,0.975
HR911105A = drill 0.813 pad 1.524 square: 1 4.445,-6.35 | drill 0.813 pad 1.524 round: 2 3.175,-8.89; 3 1.905,-6.35; 4 0.635,-8.89; 5 -0.635,-6.35; 6 -1.905,-8.89; 7 -3.175,-6.35; 8 -4.445,-8.89; 9 6.604,4.902; 10 4.064,4.902; 11 -4.064,4.902; 12 -6.604,4.902 | drill 1.651 pad 2.159 round: 13 8.001,-3.175; 14 -8.001,-3.175 | hole 3.2: 5.715,0; -5.715,0
STAND-OFF = hole 3.302: 0,0
WE-KI_0805_B = smd 1.02 x 1.78: 1 -0.89,0; 2 0.89,0
MS85 = smd 4.5 x 2.25: 1 0,-3.383; 2 0,3.383
CHIPLED_0805 = smd 1.2 x 1.2: A 0,-1.05; C 0,1.05
TC26H = drill 0.813 round: 1 -1.27,0; 2 1.27,0
R0603 = smd 1 x 1.1: 1 -0.85,0; 2 0.85,0
RN8P-4R-CRA06S = smd 0.63 x 1.15: 1 -1.295,-0.975; 4 1.295,-0.975; 5 1.295,0.975; 8 -1.295,0.975 | smd 0.44 x 1.15: 2 -0.4,-0.975; 3 0.4,-0.975; 6 0.4,0.975; 7 -0.4,0.975
SJ_2S-NO = smd 0.635 x 1.27: 1 -0.45,0; 2 0.45,0
MA07-2 = drill 1.016 octagon: 1 -7.62,-1.27; 2 -7.62,1.27; 3 -5.08,-1.27; 4 -5.08,1.27; 5 -2.54,-1.27; 6 -2.54,1.27; 7 0,-1.27; 8 0,1.27; 9 2.54,-1.27; 10 2.54,1.27; 11 5.08,-1.27; 12 5.08,1.27; 13 7.62,-1.27; 14 7.62,1.27
TACT_SWITCH_SMALL = smd 1.651 x 0.762: 1 -2.54,1.905; 2 2.54,1.905; 3 -2.54,-1.905; 4 2.54,-1.905
SO08W = smd 0.6 x 2.2: 1 -1.905,-4.6; 2 -0.635,-4.6; 3 0.635,-4.6; 4 1.905,-4.6; 5 1.905,4.6; 6 0.635,4.6; 7 -0.635,4.6; 8 -1.905,4.6
PQFP208 = smd 1.5 x 0.32: 1 -15.3,12.75; 2 -15.3,12.25; 3 -15.3,11.75; 4 -15.3,11.25; 5 -15.3,10.75; 6 -15.3,10.25; 7 -15.3,9.75; 8 -15.3,9.25; 9 -15.3,8.75; 10 -15.3,8.25; 11 -15.3,7.75; 12 -15.3,7.25; 13 -15.3,6.75; 14 -15.3,6.25; 15 -15.3,5.75; 16 -15.3,5.25; 17 -15.3,4.75; 18 -15.3,4.25; 19 -15.3,3.75; 20 -15.3,3.25; 21 -15.3,2.75; 22 -15.3,2.25; 23 -15.3,1.75; 24 -15.3,1.25; 25 -15.3,0.75; 26 -15.3,0.25; 27 -15.3,-0.25; 28 -15.3,-0.75; 29 -15.3,-1.25; 30 -15.3,-1.75; 31 -15.3,-2.25; 32 -15.3,-2.75; 33 -15.3,-3.25; 34 -15.3,-3.75; 35 -15.3,-4.25; 36 -15.3,-4.75; 37 -15.3,-5.25; 38 -15.3,-5.75; 39 -15.3,-6.25; 40 -15.3,-6.75; 41 -15.3,-7.25; 42 -15.3,-7.75; 43 -15.3,-8.25; 44 -15.3,-8.75; 45 -15.3,-9.25; 46 -15.3,-9.75; 47 -15.3,-10.25; 48 -15.3,-10.75; 49 -15.3,-11.25; 50 -15.3,-11.75; 51 -15.3,-12.25; 52 -15.3,-12.75; 105 15.3,-12.75; 106 15.3,-12.25; 107 15.3,-11.75; 108 15.3,-11.25; 109 15.3,-10.75; 110 15.3,-10.25; 111 15.3,-9.75; 112 15.3,-9.25; 113 15.3,-8.75; 114 15.3,-8.25; 115 15.3,-7.75; 116 15.3,-7.25; 117 15.3,-6.75; 118 15.3,-6.25; 119 15.3,-5.75; 120 15.3,-5.25; 121 15.3,-4.75; 122 15.3,-4.25; 123 15.3,-3.75; 124 15.3,-3.25; 125 15.3,-2.75; 126 15.3,-2.25; 127 15.3,-1.75; 128 15.3,-1.25; 129 15.3,-0.75; 130 15.3,-0.25; 131 15.3,0.25; 132 15.3,0.75; 133 15.3,1.25; 134 15.3,1.75; 135 15.3,2.25; 136 15.3,2.75; 137 15.3,3.25; 138 15.3,3.75; 139 15.3,4.25; 140 15.3,4.75; 141 15.3,5.25; 142 15.3,5.75; 143 15.3,6.25; 144 15.3,6.75; 145 15.3,7.25; 146 15.3,7.75; 147 15.3,8.25; 148 15.3,8.75; 149 15.3,9.25; 150 15.3,9.75; 151 15.3,10.25; 152 15.3,10.75; 153 15.3,11.25; 154 15.3,11.75; 155 15.3,12.25; 156 15.3,12.75 | smd 0.32 x 1.5: 53 -12.75,-15.3; 54 -12.25,-15.3; 55 -11.75,-15.3; 56 -11.25,-15.3; 57 -10.75,-15.3; 58 -10.25,-15.3; 59 -9.75,-15.3; 60 -9.25,-15.3; 61 -8.75,-15.3; 62 -8.25,-15.3; 63 -7.75,-15.3; 64 -7.25,-15.3; 65 -6.75,-15.3; 66 -6.25,-15.3; 67 -5.75,-15.3; 68 -5.25,-15.3; 69 -4.75,-15.3; 70 -4.25,-15.3; 71 -3.75,-15.3; 72 -3.25,-15.3; 73 -2.75,-15.3; 74 -2.25,-15.3; 75 -1.75,-15.3; 76 -1.25,-15.3; 77 -0.75,-15.3; 78 -0.25,-15.3; 79 0.25,-15.3; 80 0.75,-15.3; 81 1.25,-15.3; 82 1.75,-15.3; 83 2.25,-15.3; 84 2.75,-15.3; 85 3.25,-15.3; 86 3.75,-15.3; 87 4.25,-15.3; 88 4.75,-15.3; 89 5.25,-15.3; 90 5.75,-15.3; 91 6.25,-15.3; 92 6.75,-15.3; 93 7.25,-15.3; 94 7.75,-15.3; 95 8.25,-15.3; 96 8.75,-15.3; 97 9.25,-15.3; 98 9.75,-15.3; 99 10.25,-15.3; 100 10.75,-15.3; 101 11.25,-15.3; 102 11.75,-15.3; 103 12.25,-15.3; 104 12.75,-15.3; 157 12.75,15.3; 158 12.25,15.3; 159 11.75,15.3; 160 11.25,15.3; 161 10.75,15.3; 162 10.25,15.3; 163 9.75,15.3; 164 9.25,15.3; 165 8.75,15.3; 166 8.25,15.3; 167 7.75,15.3; 168 7.25,15.3; 169 6.75,15.3; 170 6.25,15.3; 171 5.75,15.3; 172 5.25,15.3; 173 4.75,15.3; 174 4.25,15.3; 175 3.75,15.3; 176 3.25,15.3; 177 2.75,15.3; 178 2.25,15.3; 179 1.75,15.3; 180 1.25,15.3; 181 0.75,15.3; 182 0.25,15.3; 183 -0.25,15.3; 184 -0.75,15.3; 185 -1.25,15.3; 186 -1.75,15.3; 187 -2.25,15.3; 188 -2.75,15.3; 189 -3.25,15.3; 190 -3.75,15.3; 191 -4.25,15.3; 192 -4.75,15.3; 193 -5.25,15.3; 194 -5.75,15.3; 195 -6.25,15.3; 196 -6.75,15.3; 197 -7.25,15.3; 198 -7.75,15.3; 199 -8.25,15.3; 200 -8.75,15.3; 201 -9.25,15.3; 202 -9.75,15.3; 203 -10.25,15.3; 204 -10.75,15.3; 205 -11.25,15.3; 206 -11.75,15.3; 207 -12.25,15.3; 208 -12.75,15.3
48PIN-TQFN = smd 1 x 0.22: P$1 -4,2.75; P$2 -4,2.25; P$3 -4,1.75; P$4 -4,1.25; P$5 -4,0.75; P$6 -4,0.25; P$7 -4,-0.25; P$8 -4,-0.75; P$9 -4,-1.25; P$10 -4,-1.75; P$11 -4,-2.25; P$12 -4,-2.75; P$25 4,-2.75; P$26 4,-2.25; P$27 4,-1.75; P$28 4,-1.25; P$29 4,-0.75; P$30 4,-0.25; P$31 4,0.25; P$32 4,0.75; P$33 4,1.25; P$34 4,1.75; P$35 4,2.25; P$36 4,2.75 | smd 0.22 x 1: P$13 -2.75,-4; P$14 -2.25,-4; P$15 -1.75,-4; P$16 -1.25,-4; P$17 -0.75,-4; P$18 -0.25,-4; P$19 0.25,-4; P$20 0.75,-4; P$21 1.25,-4; P$22 1.75,-4; P$23 2.25,-4; P$24 2.75,-4; P$37 2.75,4; P$38 2.25,4; P$39 1.75,4; P$40 1.25,4; P$41 0.75,4; P$42 0.25,4; P$43 -0.25,4; P$44 -0.75,4; P$45 -1.25,4; P$46 -1.75,4; P$47 -2.25,4; P$48 -2.75,4
POWER_JACK_SMD = smd 2.8 x 2.4: GND 0,-5.7; P$4 6.1,-5.7; VIN0 0,5.7; VIN1 6.1,5.7 | hole 1.6: 0,0; 5.08,0
MICROSD = smd 1.27 x 0.508: 1 0,-7.645; 2 0,-6.553; 3 0,-5.461; 4 0,-4.369; 5 0,-3.277; 6 0,-2.184; 7 0,-1.092; 8 0,0; 9 0,-8.738; 10 0,-9.83 | smd 1.778 x 1.016: RSV1 -7.62,2.286; RSV2 -7.62,-11.938 | hole 1.524: -3.048,-9.906; -3.048,0.254
SOT-23-5 = smd 0.55 x 1.2: 1 -0.95,-1.3; 2 0,-1.3; 3 0.95,-1.3; 4 0.95,1.3; 5 -0.95,1.3
USB-MB-S = smd 2.5 x 0.5: D+ 2.5,0; D- 2.5,0.8; GND 2.5,-1.6; ID 2.5,-0.8; VBUS 2.5,1.6 | smd 2.5 x 2: P$1 -3,-4.5; P$2 -3,4.5; P$3 2.5,-4.4; P$4 2.5,4.5 | drill 0.9 round: P$5 0,2.2; P$6 0,-2.2
USB-A-H = drill 0.914 round: D+ 2.718,-1.003; D- 2.718,1.003; GND 2.718,-3.493; VBUS 2.718,3.493 | drill 2.311 round: P$5 0,-6.566; P$6 0,6.566
5X8 = smd 2.032 x 2.032: 1 -3.429,0; 2 3.429,0
PAK100/2500-30 = drill 1 pad 1.422 round: 1 -17.78,-1.27; 2 -17.78,1.27; 3 -15.24,-1.27; 4 -15.24,1.27; 5 -12.7,-1.27; 6 -12.7,1.27; 7 -10.16,-1.27; 8 -10.16,1.27; 9 -7.62,-1.27; 10 -7.62,1.27; 11 -5.08,-1.27; 12 -5.08,1.27; 13 -2.54,-1.27; 14 -2.54,1.27; 15 0,-1.27; 16 0,1.27; 17 2.54,-1.27; 18 2.54,1.27; 19 5.08,-1.27; 20 5.08,1.27; 21 7.62,-1.27; 22 7.62,1.27; 23 10.16,-1.27; 24 10.16,1.27; 25 12.7,-1.27; 26 12.7,1.27; 27 15.24,-1.27; 28 15.24,1.27; 29 17.78,-1.27; 30 17.78,1.27

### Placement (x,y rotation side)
BATT1  43.18,10.41 0 bottom
C1  38.61,16 90 top
C2  41.91,16 90 top
C3  35.56,12.45 270 top
C4  21.08,14.99 180 top
C5  25.65,17.53 90 top
C6  60.2,60.71 0 top
C7  40.64,60.45 180 top
C8  83.57,50.8 270 top
C9  71.37,50.55 0 top
C10  25.91,33.78 0 top
C11  25.91,27.69 0 top
C12  31.75,69.6 270 top
C13  32.77,37.59 180 top
C14  51.82,23.37 270 top
C15  67.82,58.93 90 top
C16  56.9,61.47 90 top
C17  33.02,53.85 180 top
C18  33.02,49.28 180 top
C19  32.77,43.69 180 top
C20  32.77,39.62 180 top
C21  37.34,26.67 270 top
C22  50.29,60.71 180 top
C23  44.45,61.21 90 top
C24  76.71,58.93 0 top
C25  73.15,59.18 0 top
C26  33.78,69.6 270 top
C27  74.93,49.02 0 top
C28  76.96,55.63 270 top
C29  74.93,55.63 270 top
C30  72.9,55.63 270 top
C31  70.87,58.42 180 top
C32  81.03,41.4 90 top
C33  90.68,24.13 270 top
C34  54.86,8.89 90 top
C35  74.93,46.99 180 top
C36  42.16,76.71 90 top
C37  70.87,43.43 0 top
C38  84.07,59.18 180 top
C39  86.61,70.61 0 top
C40  70.61,34.54 0 top
C41  97.79,68.83 180 top
C42  84.07,45.21 0 top
C43  87.63,52.32 90 top
C44  58.67,25.15 270 top
C45  68.07,27.69 270 top
C46  68.07,17.78 270 top
C47  67.31,5.84 0 top
C48  68.07,24.13 90 top
C49  68.07,21.08 270 top
C50  83.06,17.53 90 top
C51  83.06,24.13 270 top
C52  44.7,76.71 90 top
C53  45.72,23.37 270 top
C54  67.82,62.23 90 top
C55  36.58,71.12 180 top
C56  36.58,69.09 180 top
C57  50.29,68.83 180 top
C58  50.29,64.77 0 top
C59  48.26,62.74 180 top
C60  28.7,61.21 90 top
C61  34.54,61.21 270 top
C62  60.2,62.74 180 top
C63  14.22,14.73 180 top
C74  82.3,62.48 90 top
C75  25.15,73.15 90 top
D1  96.77,24.38 270 top
D2  93.47,67.82 90 top
F1  97.79,70.87 180 top
IC1  91.19,34.04 270 top
IC2  75.44,16.51 270 top
IC3  97.79,65.79 180 top
IC4  84.07,54.1 0 top
J4  14.22,71.63 0 top
JP1  97.54,77.22 0 top
JP2  2.79,77.22 0 top
JP3  97.54,2.79 0 top
JP4  2.79,2.79 0 top
L1  30.99,61.21 270 top
L2  29.72,69.6 270 top
L3  36.58,73.15 0 top
L4  50.29,70.87 0 top
L5  86.61,65.79 90 top
LED1  77.98,47.75 90 top
LED2  77.98,44.96 90 top
LED3  77.98,42.16 90 top
LINK/ACT  33.53,76.96 180 top
Q1  31.5,30.73 90 top
Q2  84.07,41.4 270 top
R1  41.66,12.45 90 top
R2  39.62,12.45 90 top
R3  21.59,17.53 90 top
R4  23.62,17.53 90 top
R4A  27.43,73.15 90 top
R5  55.88,74.68 90 top
R5A  31.5,73.15 90 top
R6  66.29,22.35 90 top
R7  19.56,17.53 270 top
R8  24.13,14.99 180 top
R9  50.29,66.8 180 top
R10  27.43,69.6 90 top
R11  37.59,12.45 90 top
R12  36.58,16 90 top
R13  86.11,62.48 270 top
R14  32.77,34.8 0 top
R15  36.58,61.21 90 top
R16  73.91,47.75 180 top
R17  73.91,44.96 180 top
R18  64.52,74.68 90 top
R19  71.63,45.97 90 top
R20  70.87,55.63 90 top
R21  71.63,49.02 270 top
R22  73.91,42.16 180 top
R23  78.99,46.99 270 top
R24  25.15,69.6 90 top
R25  29.46,36.32 0 top
R26  26.42,61.21 270 top
R27  52.83,8.89 270 top
R28  24.13,61.21 270 top
R29  87.63,59.18 90 top
R30  78.99,43.43 270 top
R31  83.06,10.92 270 top
R32  84.07,51.05 0 top
R33  84.07,48.51 0 top
R34  80.77,49.78 270 top
R35  33.53,73.15 90 top
R36  29.46,73.15 90 top
RN2  20.32,35.81 0 top
SJ1  64.52,65.28 270 top
SJ3  29.46,34.04 270 top
SJ6  55.88,65.28 270 top
SPEED  29.46,76.96 180 top
SV1  15.24,24.89 90 top
SW1  54.36,3.81 0 top
U1  60.2,70.1 180 top
U2  68.83,70.1 180 top
U3  52.58,42.93 0 top
U$1  43.43,67.82 0 top
U$2  96.77,13.21 180 top
USD  87.63,67.31 270 top
VR1  74.93,44.2 90 top
WAKE  74.93,39.12 180 top
X1  40.64,5.59 90 top
X2  22.61,9.91 90 top
X3  77.72,50.8 0 top
X4  6.35,35.31 90 top

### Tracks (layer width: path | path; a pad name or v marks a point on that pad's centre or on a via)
1.8V  (11 unrouted)
  Top 0.254: U3.203 42.33,59.61 C7.1 | U3.174 56.83,60.55 C16.1 | U3.38 36.23,37.18 35.81,37.59 C13.1 | U3.77 C14.1
  Top 0.61: C42.+ 81.28,45.21 80.77,45.72 R34.2 81.19,48.51 R33.1
3.3V  (via drill 0.51)  (36 unrouted)
  Top 0.254: LINK/ACT.A 33.53,78.23 29.68,78.23 SPEED.A 29.46,78.23 20.83,78.23 | 20.83,78.23 7.87,78.23 7.62,77.98 J4.12 | 20.83,78.23 J4.9 | v64.52,76.71 R18.2 | R5.2 v55.88,76.71 47.75,76.71 44.68,73.64 U$1.P$40 | 83.31,61.72 86.02,61.72 R13.2 | C74.1 82.3,61.72 83.31,61.72 | 83.31,61.72 83.31,67.26 USD.4 | U$1.P$26 48.64,65.57 C58.1 49.53,64.68 49.53,62.74 C59.1 47.43,64.75 U$1.P$25 | U3.199 44.33,59.99 C23.1 | U1.6 59.56,62.95 C62.2 59.44,62.74 59.44,60.79 C6.1 59.33,60.69 U3.169 | U3.13 35.2,49.68 34.8,49.28 C18.1 | U3.24 35.03,44.18 34.54,43.69 C19.1 | U3.32 36.37,40.18 35.81,39.62 C20.1 | C21.1 37.34,30.12 U3.52 | 15.24,17.27 SV1.2 | 15.24,17.27 SV1.1 | U3.132 70.02,43.68 C37.1 | U3.5 34.12,53.68 C17.1 | U3.65 45.83,24.22 C53.1 | RN2.5 RN2.6 RN2.7 RN2.8 | U3.157 65.33,59.69 | U3.160 63.83,59.69 65.33,59.69 | C54.2 65.33,63.08 65.33,59.69 | C54.2 68.2,63.08 | U2.6 68.2,64.77 68.07,64.77 68.07,63.08 C54.2 | IC2.49 82.97,22.91 C51.2 | IC2.1 68.07,26.91 C45.2 68.07,25.4 68.16,25.31 68.4,25.31 | IC2.14 68.07,16.51 C46.2 | IC2.27 68.43,6.11 C47.2 | 68.4,25.31 IC2.3 | C48.2 68.4,25.31 | IC2.9 68.35,20.51 C49.2 | IC2.43 82.89,18.11 C50.2 | C63.1 15.24,14.73 15.24,17.27
  Top 0.305: IC1.4 92.79,62.66 92.71,62.74 83.23,62.74 | IC4.3 82.99,53.78 83.31,54.1 83.31,59.18 C38.+ | 49.53,62.74 v51.31,62.74 51.31,60.71 C22.1 51.05,60.62 51.05,59.94 50.33,59.22 U3.187
  Top 0.61: L5.2 83.23,62.74 83.23,59.64 C38.+
  Bottom 0.254: v55.88,76.71 v64.52,76.71
  Bottom 0.305: v51.31,62.74 51.31,72.14 v55.88,76.71
5V
  Top 0.305: IC3.2 96.84,66.99 96.77,67.06 96.77,68.67 C41.2 96.77,68.83 96.77,70.7 F1.2
CCT  (1 unrouted)
  Top 0.254: J4.5 13.59,64.01 J4.4 17.23,60.36 R28.2 R26.2 C60.1
D0
  Top 0.254: IC2.2 70.31,26.11 70.61,26.42 70.61,28.7 68.64,30.68 U3.106
D1
  Top 0.254: IC2.4 70.48,24.51 71.12,25.15 71.12,28.96 68.9,31.18 U3.107
D2
  Top 0.254: IC2.5 70.7,23.71 71.63,24.64 71.63,29.72 69.67,31.68 U3.108
D3
  Top 0.254: IC2.7 70.37,22.11 72.14,23.88 72.14,29.97 69.93,32.18 U3.109
D4
  Top 0.254: IC2.8 70.33,21.31 72.64,23.62 72.64,30.23 70.19,32.68 U3.110
D5
  Top 0.254: IC2.10 70.51,19.71 73.15,22.35 73.15,30.48 70.46,33.18 U3.111
D6
  Top 0.254: IC2.11 70.47,18.91 73.66,22.1 73.66,30.73 70.72,33.68 U3.112
D7  (via drill 0.51)
  Top 0.254: U3.118 73.56,36.68 75.95,34.29 v75.95,17.78 | IC2.13 72.43,17.31 v72.64,17.53
  Bottom 0.254: v72.64,17.53 75.69,17.53 v75.95,17.78
D8
  Top 0.254: IC2.42 80.48,17.31 76.45,21.34 76.45,34.54 73.82,37.18 U3.119
D9
  Top 0.254: IC2.44 80.4,18.91 76.96,22.35 76.96,34.8 74.08,37.68 U3.120
D10
  Top 0.254: IC2.45 80.37,19.71 77.47,22.61 77.47,35.31 74.6,38.18 U3.121
D11
  Top 0.254: IC2.47 80.54,21.31 77.98,23.88 77.98,35.56 74.86,38.68 U3.122
D12
  Top 0.254: IC2.48 80.51,22.11 78.49,24.13 78.49,35.81 75.12,39.18 U3.123
D13
  Top 0.254: IC2.50 80.43,23.71 78.99,25.15 78.99,36.07 75.39,39.68 U3.124
D14
  Top 0.254: IC2.51 80.65,24.51 79.5,25.65 79.5,36.32 75.65,40.18 U3.125
D15
  Top 0.254: IC2.53 80.32,26.11 80.01,26.42 80.01,36.58 75.91,40.68 U3.126
GND  (19 unrouted)
  Top 0.254: IC2.12 69.01,18.11 68.58,18.54 68.16,18.54 C46.1 | 68.07,26.42 C45.1
  pour Bottom (rank 6): 0,80.01 100.33,80.01 100.33,0 0,0
  pour Top (rank 6): 0,80.01 100.33,80.01 100.33,-1.02 0,-1.02
LED_A
  Top 0.254: R5A.1 R35.1 34.46,72.3 34.54,72.39 34.54,74.93 35.05,75.44 40.13,75.44 43.18,72.39 U$1.P$43
LED_B  (via drill 0.51)
  Top 0.254: R4A.1 R36.1 30.39,72.3 30.48,72.39 30.48,76.71 30.73,76.96 v31.5,76.96 | U$1.P$42 43.68,72.65 39.37,76.96 v37.59,76.96
  Bottom 0.254: v31.5,76.96 v37.59,76.96
LED_SPEED
  Top 0.254: J4.10 18.29,75.44 18.54,75.18 27.18,75.18 27.43,74.93 R4A.2
N$1  (via drill 0.38)
  Top 0.254: U3.35 36.14,38.68 v36.07,38.61 | SV1.3 21.61,24.92 v21.61,31.75 RN2.4
  Bottom 0.254: v21.61,31.75 21.61,33.55 26.67,38.61 v36.07,38.61
N$2
  Top 0.254: U3.45 35.71,33.68 34.04,32 Q1.2 28.54,32 C10.2
N$3
  Top 0.254: U3.46 36.22,33.18 32.51,29.46 Q1.1 28.54,29.46 C11.2
N$4
  Top 0.254: U3.149 68.73,52.18 69.34,51.56 72.39,51.56 | 72.39,51.56 74.17,51.56 74.17,50.93 X3.1 | C9.2 72.39,50.8 72.39,51.56
N$5
  Top 0.254: U3.150 80.67,52.68 81.03,52.32 81.03,50.93 X3.2 82.72,50.8 C8.2
N$6
  Top 0.254: U3.151 68.67,53.18 69.09,53.59 74.68,53.59 74.93,53.85 C29.2
N$7
  Top 0.254: IC2.18 67.46,13.31 67.06,13.72 67.06,29.97 67.26,30.18 U3.105
N$8  (via drill 0.51)
  Top 0.254: U3.104 65.33,15.19 v66.04,14.48 | IC2.17 70.98,14.11 v71.12,13.97
  Bottom 0.254: v66.04,14.48 66.29,14.22 70.87,14.22 v71.12,13.97
N$9
  Top 0.254: U3.116 72.78,35.68 74.68,33.78 74.68,15.24 74.35,14.91 IC2.16
N$10  (via drill 0.51)
  Top 0.254: U3.99 62.83,26.58 62.99,26.42 62.99,16 v63.25,15.75 | IC2.15 68.36,15.71 v68.33,15.75
  Bottom 0.254: v63.25,15.75 v68.33,15.75
N$11
  Top 0.254: IC2.23 66.64,9.31 62.48,13.46 62.48,26.16 62.33,26.32 U3.98
N$12
  Top 0.254: IC2.24 66.42,8.51 61.98,12.95 61.98,25.91 61.83,26.06 U3.97
N$29  (via drill 0.51)
  Top 0.254: U3.81 53.83,25.67 56.39,23.11 56.39,13.46 v55.63,12.7 | IC2.20 70.89,11.71 v71.12,11.94
  Bottom 0.254: v55.63,12.7 55.88,12.45 67.56,12.45 68.07,11.94 v71.12,11.94
N$30  (via drill 0.51)
  Top 0.254: IC2.21 67.58,10.91 66.55,11.94 65.28,11.94 v64.01,13.21 | U3.80 53.33,25.41 55.88,22.86 55.88,14.22 v55.63,13.97
  Bottom 0.254: v55.63,13.97 56.39,13.21 v64.01,13.21
N$31  (via drill 0.51)
  Top 0.254: U3.115 72.01,35.18 74.17,33.02 74.17,16 v73.91,15.75 | IC2.38 80.12,14.11 v80.01,14.22
  Bottom 0.254: v80.01,14.22 75.18,14.22 v73.91,15.75
N$32
  Top 0.254: IC2.25 66.2,7.71 61.47,12.45 61.47,25.65 61.33,25.79 U3.96
N$33
  Top 0.254: IC2.26 65.99,6.91 60.96,11.94 60.96,25.4 60.83,25.53 U3.95
N$34  (via drill 0.51)
  Top 0.254: U3.191 48.33,55.81 51.05,53.09 v51.56,53.09 | USD.1 79.98,66.27 77.22,63.5 v77.22,61.72
  Bottom 0.254: v51.56,53.09 61.47,53.09 70.36,61.98 76.96,61.98 v77.22,61.72
N$35
  Top 0.254: X2.D+ 23.61,14.66 R8.2 23.62,15.33 R4.1 23.62,16.76 25.57,16.76 C5.1
N$36
  Top 0.254: U3.51 35.92,30.68 R4.2
N$37
  Top 0.254: U3.43 35.18,34.68 34.09,33.59 SJ3.2
N$38
  Top 0.254: U3.50 35.75,31.18 24.13,19.56 22.77,19.56 R3.2
N$39
  Top 0.254: U3.181 53.33,70.35 53.59,70.61 60.71,70.61 | 60.71,70.61 69.34,70.61 69.47,70.74 U2.2 | U1.2 60.73,74.7 60.71,74.68 60.71,70.61
N$40
  Top 0.305: IC1.5 91.08,59.33 90.17,58.42 87.72,58.42 R29.1 87.63,54.61 87.45,54.43 IC4.7 88.58,54.43 88.65,54.36 88.65,43.69 86.36,41.4 Q2.3
N$41  (via drill 0.51)
  Top 0.254: U3.180 53.83,69.07 54.1,69.34 v61.98,69.34 70.36,69.34 70.74,69.72 U2.1 | U1.1 62,74.7 61.98,74.68 v61.98,72.14
  Bottom 0.254: v61.98,69.34 v61.98,72.14
N$42  (via drill 0.51)
  Top 0.254: C61.2 34.54,60.45 35.56,60.45 | 35.56,60.45 36.49,60.45 | 36.49,60.45 R15.1 36.58,60.45 36.49,60.45 | 35.56,60.45 v35.56,59.18 | U$1.P$16 42.18,64.5 v41.4,65.28
  Bottom 0.254: v35.56,59.18 35.81,59.18 41.4,64.77 v41.4,65.28
N$43
  Top 0.254: X4.18 6.35,39.12 8.89,39.12 14.45,44.68 U3.23
N$44
  Top 0.254: X4.17 8.89,37.85 13.72,42.67 34.29,42.67 34.79,43.18 U3.26
N$45
  Top 0.254: U3.179 54.33,67.79 54.61,68.07 61.98,68.07 | 61.98,68.07 70.36,68.07 70.74,67.69 U2.8 | 61.98,68.07 61.98,65.63 U1.8
N$46
  Top 0.254: U3.9 6.21,51.68 X4.28
N$47  (via drill 0.51)  (1 unrouted)
  Top 0.254: U3.37 39.29,37.68 v39.62,37.34
  Bottom 0.254: 39.12,33.02 39.62,33.53 v39.62,37.34
N$48  (via drill 0.38, 0.51)
  Top 0.254: U3.30 35.84,41.18 35.31,40.64 28.45,40.64 v27.18,39.37 | RN2.3 v20.72,32.4 20.72,26.56 SV1.5
  Bottom 0.254: v20.72,32.4 20.72,33.42 26.67,39.37 v27.18,39.37
N$49  (via drill 0.38, 0.51)
  Top 0.254: U3.31 38.83,40.68 v39.37,40.13 | RN2.2 v19.92,31.6 19.92,28.3 SV1.7
  Bottom 0.254: v39.37,40.13 26.67,40.13 19.92,33.38 v19.92,31.6
N$50  (via drill 0.38, 0.51)
  Top 0.254: U3.34 40.19,39.18 40.39,39.37 v40.39,40.64 | RN2.1 v19.02,32.23 19.02,29.95 SV1.9
  Bottom 0.254: v40.39,40.64 40.13,40.89 38.61,40.89 38.35,40.64 26.39,40.64 19.02,33.27 v19.02,32.23
N$51
  Top 0.254: U2.5 66.93,65.66 66.8,65.79 64.57,65.79 SJ1.1
N$52
  Top 0.254: X4.13 8.89,32.77 18.29,42.16 34.54,42.16 35.06,42.68 U3.27
N$53  (via drill 0.51)
  Top 0.254: U3.94 60.33,25.27 60.45,25.15 60.45,10.92 v64.26,7.11 | IC2.29 79.81,6.91 v79.76,6.86
  Bottom 0.254: v64.26,7.11 64.52,6.86 v79.76,6.86
N$54  (via drill 0.51)
  Top 0.254: U3.93 59.83,25.01 59.94,24.89 59.94,10.41 v62.74,7.62 | IC2.30 79.41,7.71 v79.25,7.87
  Bottom 0.254: v62.74,7.62 62.99,7.87 v79.25,7.87
N$55  (via drill 0.51)
  Top 0.254: U3.92 59.33,24.75 59.44,24.64 59.44,9.91 v61.21,8.13 | IC2.31 79.88,8.51 79.5,8.89 v78.99,8.89
  Bottom 0.254: v61.21,8.13 61.72,8.64 78.74,8.64 v78.99,8.89
N$56  (via drill 0.51)
  Top 0.254: U3.89 57.83,25.48 58.93,24.38 58.93,9.4 v59.69,8.64 | IC2.32 80.1,9.31 79.76,9.65 78.23,9.65 v77.98,9.4
  Bottom 0.254: v59.69,8.64 60.2,9.14 77.72,9.14 v77.98,9.4
N$57  (via drill 0.51)
  Top 0.254: U3.88 57.33,25.22 58.42,24.13 v58.42,8.89 | IC2.33 79.3,10.11 v78.99,10.41
  Bottom 0.254: v58.42,8.89 59.18,9.65 76.96,9.65 77.72,10.41 v78.99,10.41
N$58  (via drill 0.51)
  Top 0.254: U3.100 63.33,26.84 63.5,26.67 63.5,17.27 64.26,16.51 64.26,15.24 v63.5,14.48 | IC2.34 79.77,10.91 79.5,11.18 76.2,11.18 v75.69,11.68
  Bottom 0.254: v63.5,14.48 64.26,14.48 65.79,12.95 72.39,12.95 73.66,11.68 v75.69,11.68
N$59  (via drill 0.51)
  Top 0.254: U3.86 56.33,25.46 57.91,23.88 57.91,10.41 v57.66,10.16 | v66.55,10.41 67.56,10.41 67.87,10.11 IC2.22
  Bottom 0.254: v57.66,10.16 66.29,10.16 v66.55,10.41
N$60  (via drill 0.51)
  Top 0.254: U3.85 55.83,25.2 57.4,23.62 57.4,11.43 v56.64,10.67 | IC2.35 78.71,11.71 v78.49,11.94
  Bottom 0.254: v56.64,10.67 57.4,11.43 67.06,11.43 67.82,10.67 77.22,10.67 v78.49,11.94
N$61  (via drill 0.51)
  Top 0.254: U3.84 55.33,24.94 56.9,23.37 56.9,12.45 v56.13,11.68 | v83.06,8.64 R31.2
  Bottom 0.254: v56.13,11.68 56.39,11.94 67.31,11.94 67.82,11.43 70.61,11.43 70.87,11.18 76.45,11.18 77.98,12.7 82.55,12.7 83.06,12.19 v83.06,8.64
N$62
  Top 0.254: R31.1 82.46,11.77 81.72,12.51 IC2.36
N$63  (1 unrouted)
N$64
  Top 0.254: U3.182 52.83,71.12 53.34,71.63 58.17,71.63 58.29,71.75 U1.4 58.29,74.04 58.17,73.91 55.97,73.91 R5.1
N$65
  Top 0.254: X4.11 8.89,30.23 20.32,41.66 34.8,41.66 35.32,42.18 U3.28
N$66
  Top 0.254: R10.2 R24.2 C75.1
N$67
  Top 0.254: U$1.P$8 U$1.P$7 34.29,67.57 33.78,68.07 C26.2 C12.2 29.72,68.75 L2.2
N$68  (2 unrouted)
N$69
  Top 0.254: U$1.P$15 41.68,62.96 42.83,61.82 U3.202
N$70  (via drill 0.51)
  Top 0.254: R9.2 48.77,66.8 48.03,66.07 U$1.P$27 45.75,66.07 v45.72,66.04 | U3.198 44.83,56.26 v44.96,56.13
  Bottom 0.254: v44.96,56.13 45.47,56.64 45.47,65.79 v45.72,66.04
N$71  (via drill 0.51)
  Top 0.254: U3.102 64.33,17.85 v64.26,17.78 | IC2.39 76.78,14.91 v76.71,14.99
  Bottom 0.254: v64.26,17.78 64.26,17.27 64.77,16.76 74.93,16.76 v76.71,14.99
N$72
  Top 0.254: U$1.P$23 45.68,63.28 46.33,62.64 U3.195
N$73
  Top 0.254: U$1.P$22 45.18,63.02 45.83,62.38 U3.196
N$74  (via drill 0.51)
  Top 0.254: U$1.P$29 45.48,67.07 v44.45,66.04 | U3.201 43.33,56.24 v43.43,56.13
  Bottom 0.254: v44.45,66.04 44.45,57.15 v43.43,56.13
N$75
  Top 0.254: U1.5 58.29,65.66 58.17,65.79 55.94,65.79 SJ6.1
N$76  (via drill 0.51)
  Top 0.254: U$1.P$34 46.71,69.57 v44.45,67.31 | v41.91,55.63 42.16,55.37 45.21,55.37 45.72,55.88 45.72,56.9 45.33,57.29 U3.197
  Bottom 0.254: v41.91,55.63 41.91,64.77 v44.45,67.31
N$77  (via drill 0.51)
  Top 0.254: U3.193 47.33,59.27 v48.01,59.94 | v48.26,71.37 48.26,70.36 47.97,70.07 U$1.P$35
  Bottom 0.254: v48.01,59.94 48.01,71.12 v48.26,71.37
N$78  (via drill 0.51)
  Top 0.254: U$1.P$36 47.43,71.69 v47.24,71.88 | U3.194 46.83,60.29 v47.24,60.71
  Bottom 0.254: v47.24,60.71 v47.24,71.88
N$79
  Top 0.254: U3.40 30.46,36.18 R25.2
N$80  (via drill 0.51)
  Top 0.254: U3.143 66.96,49.18 v65.79,48.01 | v80.26,42.16 LED3.A
  Bottom 0.254: v80.26,42.16 80.01,42.16 77.72,44.45 v65.79,48.01
N$81
  Top 0.254: SPEED.C R36.2
N$82
  Top 0.254: U3.10 8.25,51.18 X4.27
N$83
  Top 0.254: U3.42 33.99,35.18 R14.2
N$84  (1 unrouted)
  Top 0.254: IC2.19 66.99,12.51 64.83,14.67 U3.103
N$85
  Top 0.254: U3.117 73.04,36.18 75.18,34.04 75.18,13.97 75.84,13.31 IC2.37
N$86
  Top 0.254: U$1.P$5 U$1.P$4 37.43,69.07 C56.1 C55.1 37.34,71.12 36.07,72.39 36.07,72.77 L3.1
N$87
  Top 0.254: L4.1 49.44,70.1 C57.2 48.77,68.83 48,68.07 U$1.P$31
N$88
  Top 0.254: LINK/ACT.C R35.2
N$89  (via drill 0.51)
  Top 0.254: U$1.P$6 v43.43,68.07 | C52.1 44.7,75.69 43.43,75.69 | 42.16,75.69 C36.1 42.33,75.69 43.43,75.69 | v38.61,73.15 L3.2 | L4.2 51.18,72.26 v50.29,73.15 | v43.43,74.17 43.43,75.69
  Bottom 0.254: 43.43,73.15 v43.43,68.07 41.4,68.07 38.61,70.86 v38.61,73.15 | 43.43,73.15 v43.43,74.17 | 43.43,73.15 v50.29,73.15
N$90  (via drill 0.51)
  Top 0.254: U3.144 66.19,49.68 v65.79,49.28 | v80.26,44.96 LED2.A
  Bottom 0.254: v65.79,49.28 66.55,48.51 v80.26,44.96
N$91  (2 unrouted)
N$92  (via drill 0.51)
  Top 0.254: v31.5,75.69 R5A.2
  Bottom 0.254: J4.11 10.16,75.69 10.67,75.18 31.5,75.18 v31.5,75.69
N$94  (via drill 0.51)
  Top 0.254: U3.145 66.16,50.18 v65.79,50.55 | v80.26,47.75 LED1.A
  Bottom 0.254: v65.79,50.55 67.31,49.02 77.72,45.47 80.01,47.75 v80.26,47.75
N$95
  Top 0.254: R16.1 LED1.C
N$96
  Top 0.254: 40.33,17.02 40.33,14 R2.2 | 40.33,17.02 U3.54 | C1.2 38.61,17.02 40.33,17.02
N$97
  Top 0.254: 40.83,17.02 40.83,14.04 41.57,13.3 R1.2 | 40.83,17.02 U3.55 | C2.2 41.91,17.02 40.83,17.02
N$98
  Top 0.254: R17.1 LED2.C
N$99
  Top 0.254: X1.D- 39.84,11.6 R2.1
N$100
  Top 0.254: X1.D+ 40.64,10.58 R1.1
N$101
  Top 0.254: R22.1 LED3.C
N$102
  Top 0.305: X1.VBUS 39.04,8.71 37.59,10.16 R11.1 37.5,11.68 35.56,11.68 C3.2
N$103
  Top 0.254: U3.11 9.78,50.68 8.38,49.28 6.35,49.28 X4.26
N$104
  Top 0.254: X4.25 8.64,48.01 10.81,50.18 U3.12
N$106  (2 unrouted)
N$107  (via drill 0.51)
  Top 0.254: U3.190 48.83,56.07 51.05,53.85 v52.58,53.85 | v87.63,63.25 USD.8
  Bottom 0.254: v52.58,53.85 61.47,53.85 70.1,62.48 78.74,62.48 79.25,61.98 86.36,61.98 v87.63,63.25
N$108
  Top 0.254: X4.24 6.35,46.74 8.89,46.74 10.41,48.26 34.54,48.26 34.96,48.68 U3.15
N$109
  Top 0.254: X4.23 8.89,45.47 11.18,47.75 34.8,47.75 35.22,48.18 U3.16
N$110
  Top 0.254: X4.22 6.35,44.2 8.64,44.2 11.68,47.24 35.05,47.24 35.48,47.68 U3.17
N$111
  Top 0.254: X4.21 8.89,42.93 12.7,46.74 35.31,46.74 35.75,47.18 U3.18
N$112
  Top 0.254: X4.20 6.35,41.66 8.89,41.66 13.46,46.23 35.56,46.23 36.01,46.68 U3.19
N$113
  Top 0.254: X4.19 8.89,40.39 14.22,45.72 35.81,45.72 36.27,46.18 U3.20
N$114  (via drill 0.51)
  Top 0.254: U3.158 64.83,45.52 63.5,44.2 v50.04,44.2
  Bottom 0.254: X4.10 4.83,27.69 3.3,29.21 3.3,43.94 3.56,44.2 v50.04,44.2
N$115  (via drill 0.51)
  Top 0.254: U3.159 64.33,48.07 63.25,46.99 v50.04,46.99
  Bottom 0.254: X4.9 6.35,26.42 3.56,26.42 2.79,27.18 2.79,44.96 4.57,46.74 49.78,46.74 v50.04,46.99
N$116  (via drill 0.51)
  Top 0.254: U3.21 38.56,45.68 40.39,47.5 v40.39,48.01
  Bottom 0.254: v40.39,48.01 40.39,48.26 39.37,49.28 3.81,49.28 2.29,47.75 2.29,24.64 3.05,23.88 6.35,23.88 X4.5
N$117  (via drill 0.51)
  Top 0.254: U3.22 39.33,45.18 41.66,47.5 v41.66,48.01
  Bottom 0.254: v41.66,48.01 41.66,48.77 38.61,51.82 2.54,51.82 1.78,51.05 1.78,22.61 3.05,21.34 6.35,21.34 X4.3
N$118  (via drill 0.51)
  Top 0.254: U3.62 44.33,29.84 v44.45,29.97
  Bottom 0.254: X4.15 9.14,35.31 16,42.16 43.69,42.16 44.45,41.4 v44.45,29.97
N$119  (1 unrouted)
N$120
  Top 0.254: U3.154 68.65,54.68 69.09,55.12 70.52,55.12 R20.1 70.87,55.12 72.56,55.12 C30.2
N$121  (via drill 0.51)  (1 unrouted)
  Top 0.305: F1.1 98.81,70.87 v98.81,72.14
N$122  (via drill 0.51)
  Top 0.254: v43.69,30.73 46.23,30.73 46.83,30.13 U3.67
  Bottom 0.254: X4.14 6.35,34.04 8.64,34.04 16.26,41.66 43.18,41.66 43.69,41.15 v43.69,30.73
N$123  (via drill 0.51)
  Top 0.254: v45.21,31.5 43.18,31.5 42.83,31.14 U3.59
  Bottom 0.254: X4.16 6.35,36.58 9.65,36.58 15.75,42.67 43.94,42.67 45.21,41.4 v45.21,31.5
N$124  (via drill 0.51)
  Top 0.254: U3.127 50.52,41.18 v50.04,41.66
  Bottom 0.254: X4.12 4.57,30.23 3.81,30.99 3.81,41.15 4.32,41.66 13.72,41.66 15.24,43.18 48.51,43.18 v50.04,41.66
N$125
  Top 0.254: U3.29 35.58,41.68 35.05,41.15 21.34,41.15 16.51,36.32 SV1.13
N$126
  Top 0.61: U$2.VIN0 98.69,7.51 99.57,8.38 99.57,21.84 99.06,22.35 96.94,22.35 D1.A
N$127
  Top 0.61: IC1.2 96.19,64.85 95.5,65.53 93.56,65.53 D2.C 90.42,65.62 L5.1
N$130
  Top 0.305: IC4.6 87.03,53.78 C43.2
N$131
  Top 0.305: IC4.5 86.22,51.96 86.61,51.56 87.54,51.56 C43.1
N$132
  Top 0.305: IC4.8 85.3,55.08 84.84,54.61 84.84,51.14 R32.2 84.84,51.05 84.84,48.6 R33.2
N$134
  Top 0.254: IC4.1 80.98,55.08 80.77,54.86 R34.1
N$164  (3 unrouted)
NRST  (via drill 0.51)  (1 unrouted)
  Top 0.254: U2.3 68.2,77.34 68.07,77.47 59.69,77.47 59.69,74.93 59.56,74.8 U1.3 59.46,74.7 59.44,74.68 v59.44,72.14 | SW1.1 53.47,5.71 53.85,6.1 53.85,7.87 | 53.85,7.87 54.7,7.87 C34.1 | 53.85,7.87 53,7.87 | 53,7.87 R27.2 52.83,7.87 53,7.87 | 53.85,7.87 53.85,19.05 v51.82,21.08 | U3.36 39.19,38.18 39.37,38.35 v51.82,38.35 | U$1.P$47 41.18,73.12 v40.89,73.41 | v53.59,73.15 v52.32,74.42
  Bottom 0.254: 53.59,72.14 52.83,72.14 52.32,71.63 52.32,61.47 50.29,59.44 50.29,51.05 51.82,49.53 v51.82,38.35 v51.82,21.08 14.73,21.08 12.45,18.8 6.35,18.8 X4.4 | 53.59,72.14 v59.44,72.14 | v40.89,73.41 40.89,73.66 42.42,75.18 51.56,75.18 v52.32,74.42 | 53.59,72.14 v53.59,73.15
RD+  (via drill 0.51)
  Top 0.254: J4.3 16.13,65.66 17.02,66.55 19.81,66.55 20.57,65.79 v25.15,65.79 38.61,65.79 38.89,66.07 U$1.P$10 | v25.15,67.56 R24.1
  Bottom 0.254: v25.15,65.79 v25.15,67.56
RD-
  Top 0.254: J4.6 12.32,65.91 13.46,67.06 20.32,67.06 20.81,66.57 27.43,66.57 | 27.43,66.57 U$1.P$9 | 27.43,66.57 R10.1
SDCLK  (via drill 0.51)
  Top 0.254: U3.189 49.33,56.34 51.05,54.61 v51.56,54.61 | USD.5 84.35,63.52 v84.07,63.25 86.11,63.25 R13.1
  Bottom 0.254: v51.56,54.61 61.47,54.61 69.85,62.99 78.99,62.99 79.5,62.48 83.31,62.48 v84.07,63.25
SDCS  (via drill 0.51)
  Top 0.254: U3.192 47.83,55.55 51.05,52.32 v52.58,52.32 | USD.2 81.08,65.84 78.49,63.25 v78.49,61.72
  Bottom 0.254: v52.58,52.32 61.47,52.32 70.61,61.47 76.45,61.47 76.96,60.96 78.23,60.96 78.49,61.21 v78.49,61.72
SDMISO  (via drill 0.51)
  Top 0.254: U3.185 51.33,56.37 v51.56,56.13 | USD.7 86.54,65.96 v86.36,65.79
  Bottom 0.254: v51.56,56.13 61.47,56.13 69.34,64.01 84.58,64.01 v86.36,65.79
SDMOSI  (via drill 0.51)
  Top 0.254: U3.186 50.83,55.6 51.05,55.37 v52.58,55.37 | USD.3 82.17,65.41 v80.01,63.25
  Bottom 0.254: v52.58,55.37 61.47,55.37 69.6,63.5 79.76,63.5 v80.01,63.25
SHDN  (1 unrouted)
SPI0_CS1  (1 unrouted)
  Top 0.254: U2.4 66.93,74.3 66.8,74.17 66.8,73.91 64.6,73.91 R18.1
TD+  (via drill 0.51)
  Top 0.254: v24.13,63.25 R28.1 | U$1.P$12 38.91,65.07 38.73,64.9 v24.13,64.9 19.05,64.9 J4.1 18.92,65.02
  Bottom 0.254: v24.13,64.9 v24.13,63.25
TD-
  Top 0.254: U$1.P$11 40.1,65.57 40.39,65.28 40.39,64.77 39.75,64.14 26.42,64.14 | 26.42,64.14 20.83,64.14 19.43,62.74 J4.2 | 26.42,64.14 R26.1
TWCK
  Top 0.254: U3.1 7.67,55.68 X4.30
TWD  (via drill 0.51)
  Top 0.254: U3.208 39.83,54.81 v39.62,54.61
  Bottom 0.254: X4.29 38.1,53.09 v39.62,54.61
USB_D-
  Top 0.254: X2.D- 21.6,14.66 C4.1 21.59,15.33 R3.1 21.59,16.76 19.65,16.76 R7.2
USBDETECT  (via drill 0.38)
  Top 0.254: R11.2 37.5,13.3 36.58,14.22 R12.1 35.65,15.15 v35.31,15.49 | U3.3 38.54,54.68 41.4,51.82 48.51,51.82 v52.58,47.75
  Bottom 0.254: v52.58,47.75 52.58,20.57 51.82,19.81 35.81,19.81 35.31,19.3 v35.31,15.49
VDDBU  (2 unrouted)
  Top 0.254: R19.2 R21.2 71.79,48.01 72.64,48.01 | C27.1 73.91,49.02 73.91,48.01 | C35.2 73.91,47.16 73.91,48.01 | 72.64,48.01 73.91,48.01 | VR1.5 72.83,43.25 72.64,43.43 72.64,48.01
VIN  (via drill 0.51)
  Top 0.305: v87.63,61.47 R29.2
  Top 0.61: 96.77,25.91 v99.57,25.91 | IC3.3 97.79,61.01 IC1.1 97.94,60.96 v99.57,60.96 | C33.+ 90.68,25.91 96.77,25.91 | 96.77,25.91 D1.C
  Bottom 0.305: v99.57,60.96 99.57,61.21 99.31,61.47 v87.63,61.47
  Bottom 0.61: v99.57,25.91 v99.57,60.96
